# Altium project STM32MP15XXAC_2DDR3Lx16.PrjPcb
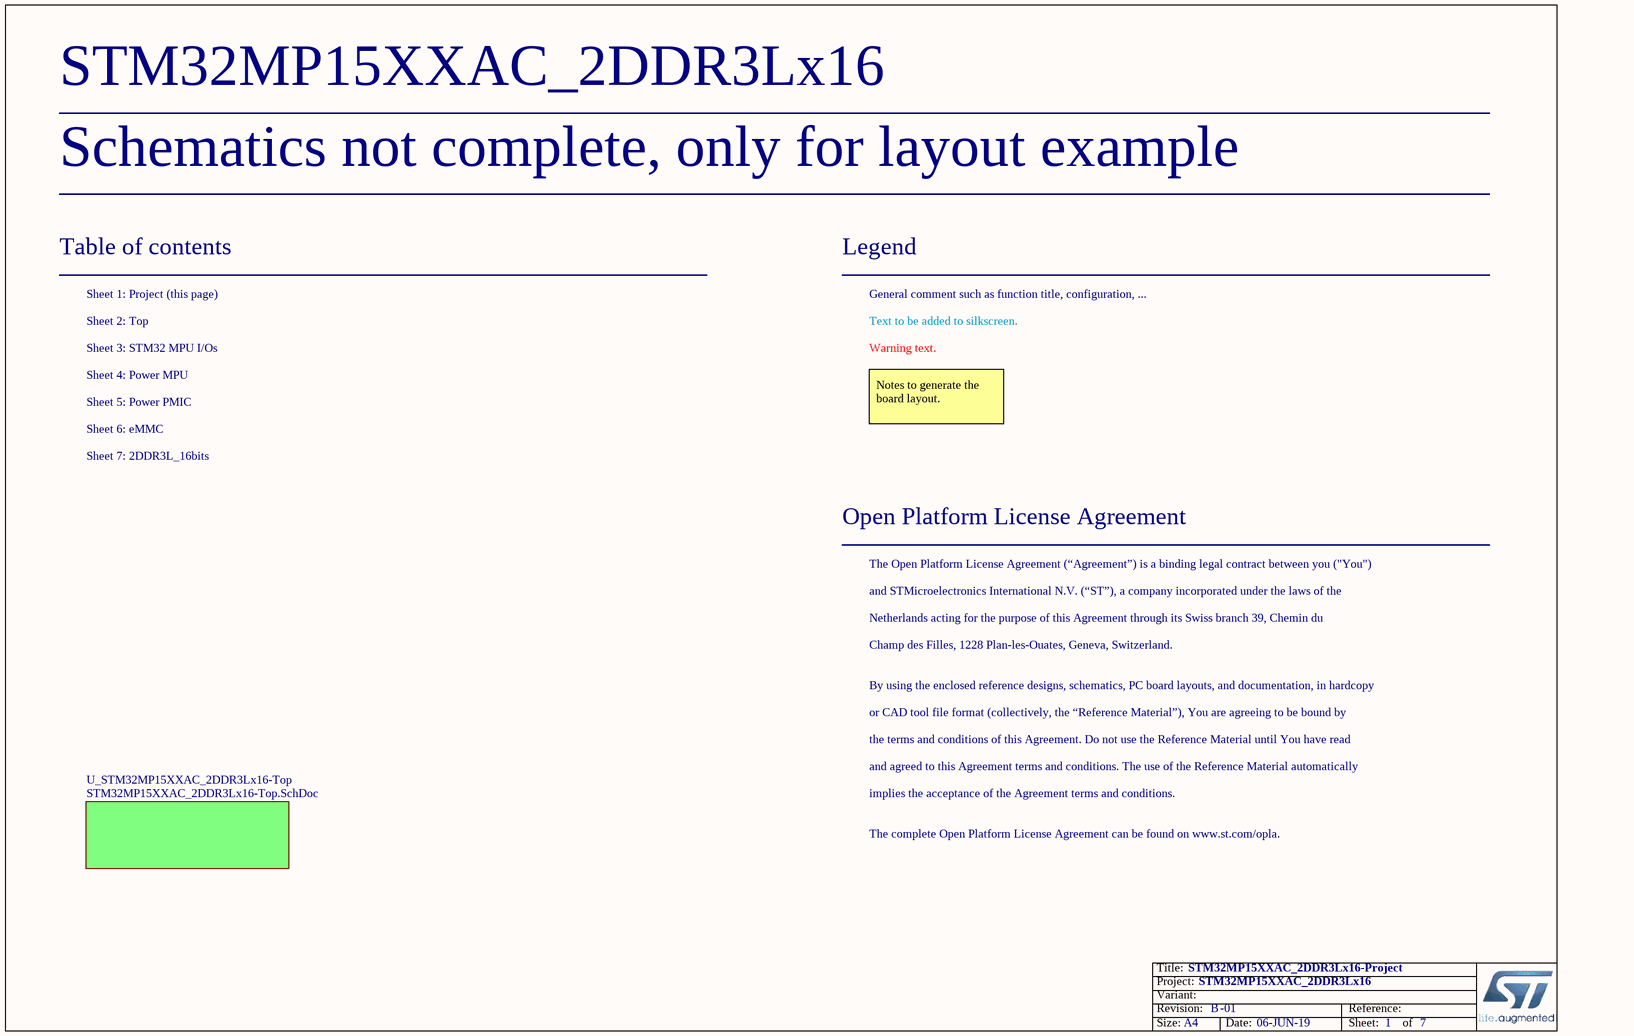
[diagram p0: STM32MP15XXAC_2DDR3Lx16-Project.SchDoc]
Board_PCB_Revision: B; Board_Name: STM32MP15XXAC_2DDR3Lx16; Board_Document_Date: 06-JUN-19; Board_Assembly_Revision: 01
7 sheets, 152 parts. Net scope: flat (ports and power ports of the same name join across sheets).
Board file: STM32MP15XXAC_2DDR3Lx16_B01.PcbDoc
Sheets:
  STM32MP15XXAC_2DDR3Lx16-Project.SchDoc
    U_STM32MP15XXAC_2DDR3Lx16-Top = STM32MP15XXAC_2DDR3Lx16-Top.SchDoc
      U_Power_PMIC = Power_PMIC.SchDoc
      U_Power_MPU = Power_MPU.SchDoc
      U_eMMC = eMMC.SchDoc
      U_STM32_MPU_IOs = STM32_MPU_IOs.SchDoc
      U_2DDR3L_16bits = 2DDR3L_16bits.SchDoc

## Sheet STM32MP15XXAC_2DDR3Lx16-Project.SchDoc: STM32MP15XXAC_2DDR3Lx16-Project
size A4; ApprovedBy: Not used; CheckedBy: Not used; Author: Not used; CompanyName: STMicroelectronics; DrawnBy: Not used; Engineer: Not used; Organization: Not used; Address1: Not used; Address2: Not used; Address3: Not used; Address4: Not used; DocumentNumber: Not used; Revision: Not used; SheetNumber: 1; SheetTotal: 7

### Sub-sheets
U_STM32MP15XXAC_2DDR3Lx16-Top = STM32MP15XXAC_2DDR3Lx16-Top.SchDoc: no entries

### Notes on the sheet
- Schematics not complete, only for layout example
- Table of contents
- Sheet 1: Project (this page)
- Legend
- General comment such as function title, configuration, ...
- Sheet 2: Top
- Sheet 3: STM32 MPU I/Os
- Sheet 4: Power MPU
- Text to be added to silkscreen.
- Warning text.
- Sheet 5: Power PMIC
- Sheet 6: eMMC
- Notes to generate the board layout.
- Sheet 7: 2DDR3L_16bits
- Open Platform License Agreement
- The Open Platform License Agreement (“Agreement”) is a binding legal contract between you ("You")
- and STMicroelectronics International N.V. (“ST”), a company incorporated under the laws of the
- Netherlands acting for the purpose of this Agreement through its Swiss branch 39, Chemin du
- Champ des Filles, 1228 Plan-les-Ouates, Geneva, Switzerland.
- By using the enclosed reference designs, schematics, PC board layouts, and documentation, in hardcopy
- or CAD tool file format (collectively, the “Reference Material”), You are agreeing to be bound by
- the terms and conditions of this Agreement. Do not use the Reference Material until You have read
- and agreed to this Agreement terms and conditions. The use of the Reference Material automatically
- implies the acceptance of the Agreement terms and conditions.
- The complete Open Platform License Agreement can be found on www.st.com/opla.

## Sheet STM32MP15XXAC_2DDR3Lx16-Top.SchDoc: STM32MP15XXAC_2DDR3Lx16-TOP
size A4; Date: Not used; ApprovedBy: Not used; CheckedBy: Not used; Author: Not used; CompanyName: STMicroelectronics; DrawnBy: Not used; Engineer: Not used; Organization: Not used; Address1: Not used; Address2: Not used; Address3: Not used; Address4: Not used; DocumentNumber: Not used; Revision: Not used; SheetNumber: 2; SheetTotal: 7
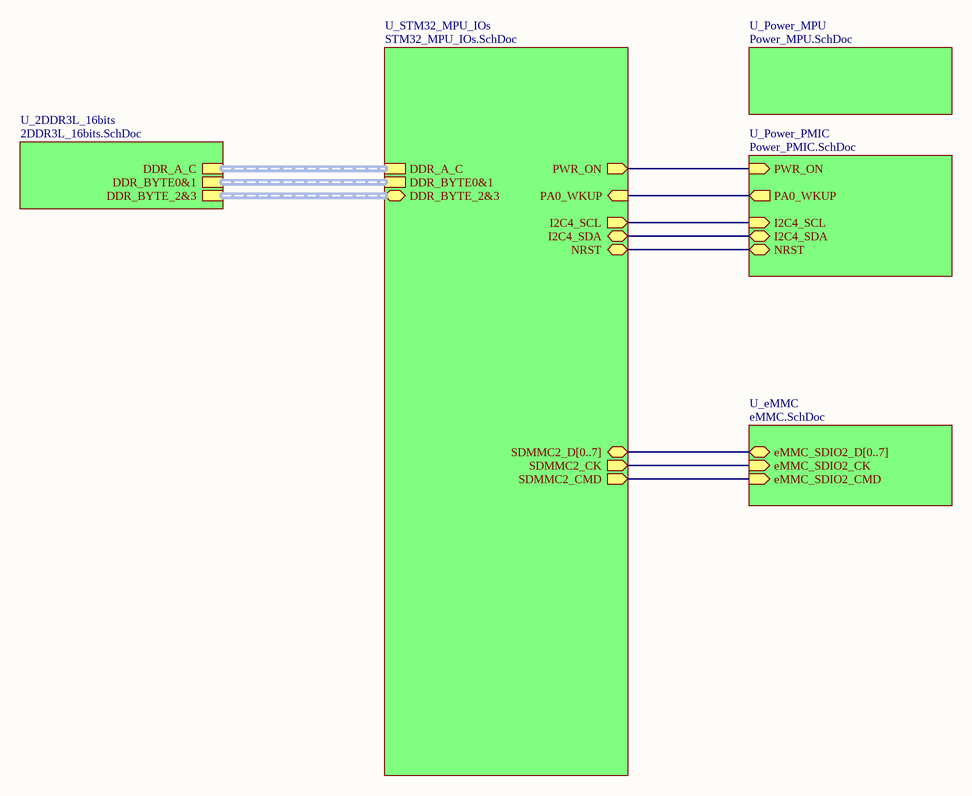
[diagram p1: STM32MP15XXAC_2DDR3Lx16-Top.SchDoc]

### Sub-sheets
U_2DDR3L_16bits = 2DDR3L_16bits.SchDoc: DDR_A_C (harness DDR_A_C), DDR_BYTE0&1 (harness DDR_BYTE_0&1), DDR_BYTE_2&3 (harness DDR_BYTE_2&3)
U_eMMC = eMMC.SchDoc: eMMC_SDIO2_CK (in), eMMC_SDIO2_D[0..7] (bidir), eMMC_SDIO2_CMD (in)
U_Power_MPU = Power_MPU.SchDoc: no entries
U_Power_PMIC = Power_PMIC.SchDoc: I2C4_SDA (bidir), I2C4_SCL (in), PA0_WKUP (out), NRST (bidir), PWR_ON (in)
U_STM32_MPU_IOs = STM32_MPU_IOs.SchDoc: PA0_WKUP (in), NRST (bidir), PWR_ON (out), I2C4_SCL (out), I2C4_SDA (bidir), DDR_BYTE0&1 (harness DDR_BYTE_0&1), DDR_A_C (harness DDR_A_C), SDMMC2_D[0..7] (bidir), SDMMC2_CMD (out), SDMMC2_CK (out), DDR_BYTE_2&3 (harness DDR_BYTE_2&3)

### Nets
(unnamed): sheet U_Power_PMIC/I2C4_SDA, sheet U_STM32_MPU_IOs/I2C4_SDA
(unnamed): sheet U_Power_PMIC/I2C4_SCL, sheet U_STM32_MPU_IOs/I2C4_SCL  [a separate net that carries the same name]
(unnamed): sheet U_Power_PMIC/PA0_WKUP, sheet U_STM32_MPU_IOs/PA0_WKUP  [a separate net that carries the same name]
(unnamed): sheet U_Power_PMIC/NRST, sheet U_STM32_MPU_IOs/NRST  [a separate net that carries the same name]
(unnamed): sheet U_Power_PMIC/PWR_ON, sheet U_STM32_MPU_IOs/PWR_ON  [a separate net that carries the same name]
(unnamed): sheet U_eMMC/eMMC_SDIO2_CK, sheet U_STM32_MPU_IOs/SDMMC2_CK  [a separate net that carries the same name]
(unnamed): sheet U_eMMC/eMMC_SDIO2_CMD, sheet U_STM32_MPU_IOs/SDMMC2_CMD  [a separate net that carries the same name]

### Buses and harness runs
bus sheet U_eMMC/eMMC_SDIO2_D[0..7] = sheet U_STM32_MPU_IOs/SDMMC2_D[0..7]
harness sheet U_2DDR3L_16bits/DDR_A_C = sheet U_STM32_MPU_IOs/DDR_A_C
harness sheet U_2DDR3L_16bits/DDR_BYTE0&1 = sheet U_STM32_MPU_IOs/DDR_BYTE0&1
harness sheet U_2DDR3L_16bits/DDR_BYTE_2&3 = sheet U_STM32_MPU_IOs/DDR_BYTE_2&3

## Sheet Power_PMIC.SchDoc: Power_PMIC
size A3; CompanyName: STMicroelectronics; Organization: Microcontrollers Division; Address1: 12, Rue Jules HOROWITZ; Address2: 38019 Grenoble; Address3: FRANCE; SheetNumber: 5; SheetTotal: 7
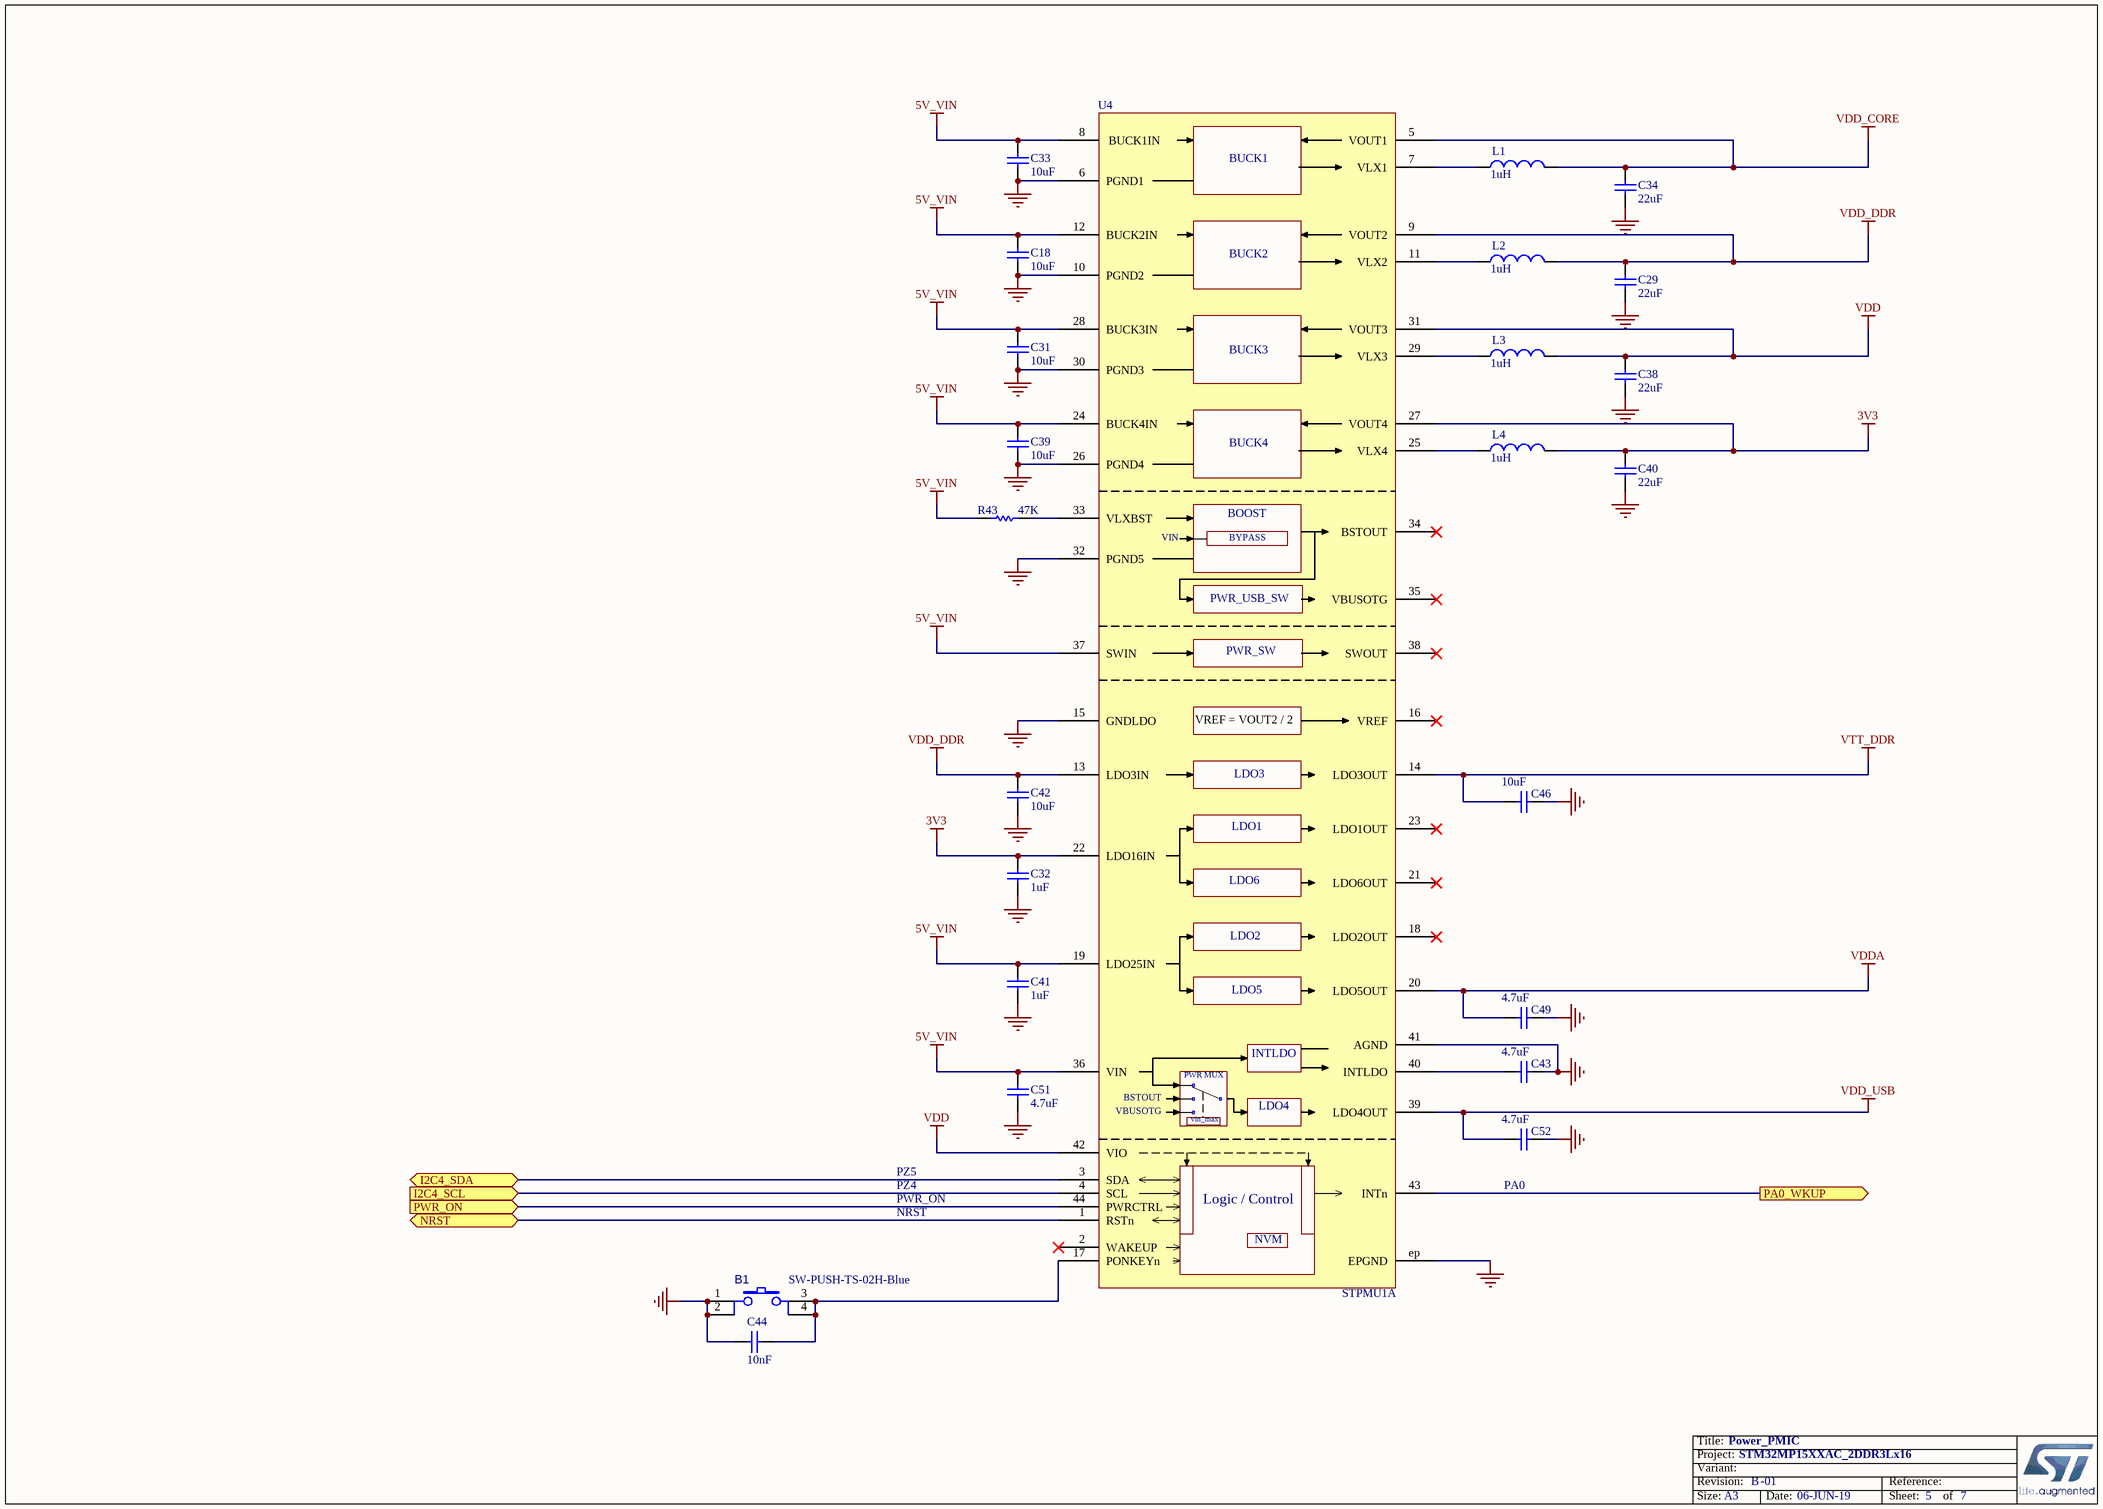
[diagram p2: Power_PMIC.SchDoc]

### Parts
B1  SW-PUSH-TS-02H-Blue  [SWI_JIUBABA_C-TS-02H-2-5-B-V-T_R_BLUE]
C18  value 10uF  [C0603]  (hidden comment: Capacitor)
C29  value 22uF  [C0603]  (hidden comment: Capacitor)
C31  value 10uF  [C0603]  (hidden comment: Capacitor)
C32  value 1uF  [C0402]  (hidden comment: Capacitor)
C33  value 10uF  [C0603]  (hidden comment: Capacitor)
C34  value 22uF  [C0603]  (hidden comment: Capacitor)
C38  value 22uF  [C0603]  (hidden comment: Capacitor)
C39  value 10uF  [C0603]  (hidden comment: Capacitor)
C40  value 22uF  [C0603]  (hidden comment: Capacitor)
C41  value 1uF  [C0402]  (hidden comment: Capacitor)
C42  value 10uF  [C0603]  (hidden comment: Capacitor)
C43  value 4.7uF  [C0402]  (hidden comment: Capacitor)
C44  value 10nF  [C0402]  (hidden comment: Capacitor)
C46  value 10uF  [C0603]  (hidden comment: Capacitor)
C49  value 4.7uF  [C0402]  (hidden comment: Capacitor)
C51  value 4.7uF  [C0402]  (hidden comment: Capacitor)
C52  value 4.7uF  [C0402]  (hidden comment: Capacitor)
L1  value 1uH  [IND_2520_TOKO_DFE252012P]  (hidden comment: IND_1uH_42mohm_3.2A)
L2  value 1uH  [IND_2520_TOKO_DFE252012P]  (hidden comment: IND_1uH_42mohm_3.2A)
L3  value 1uH  [IND_2520_TOKO_DFE252012P]  (hidden comment: IND_1uH_42mohm_3.2A)
L4  value 1uH  [IND_2520_TOKO_DFE252012P]  (hidden comment: IND_1uH_42mohm_3.2A)
R43  value 47K  [R0402]  (hidden comment: Resistor)
U4  value STPMU1A  [ICC_WFQFN44-EPAD_5X6_P040]  (hidden comment: STPMU1)

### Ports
I2C4_SCL (in), I2C4_SDA (bidir), NRST (bidir), PA0_WKUP (out), PWR_ON (in)

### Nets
3V3: C32.2 C40.2 L4.2 U4.22(LDO16IN) U4.27(VOUT4)
5V_VIN: C18.2 C31.2 C33.2 C39.2 C41.2 C51.2 R43.2 U4.8(BUCK1IN) U4.12(BUCK2IN) U4.19(LDO25IN) U4.24(BUCK4IN) U4.28(BUCK3IN) U4.36(VIN) U4.37(SWIN)
GND: B1.1 B1.2 C18.1 C29.1 C31.1 C32.1 C33.1 C34.1 C38.1 C39.1 C40.1 C41.1 C42.1 C43.2 C44.1 C46.1 C49.1 C51.1 C52.1 U4.6(PGND1) U4.10(PGND2) U4.15(GNDLDO) U4.26(PGND4) U4.30(PGND3) U4.32(PGND5) U4.41(AGND) U4.ep(EPGND)
VDD: C38.2 L3.2 U4.31(VOUT3) U4.42(VIO)
VDD_CORE: C34.2 L1.2 U4.5(VOUT1)
VDD_DDR: C29.2 C42.2 L2.2 U4.9(VOUT2) U4.13(LDO3IN)
VDD_USB: C52.2 U4.39(LDO4OUT)
VDDA: C49.2 U4.20(LDO5OUT)
VTT_DDR: C46.2 U4.14(LDO3OUT)
I2C4_SCL: U4.4(SCL) ; port I2C4_SCL
I2C4_SDA: U4.3(SDA) ; port I2C4_SDA
NRST: U4.1(RSTn) ; port NRST
PA0_WKUP: U4.43(INTn) ; port PA0_WKUP
PWR_ON: U4.44(PWRCTRL) ; port PWR_ON
NetB1_3: B1.3 B1.4 C44.2 U4.17(PONKEYn)
NetC43_1: C43.1 U4.40(INTLDO)
NetL1_1: L1.1 U4.7(VLX1)
NetL2_1: L2.1 U4.11(VLX2)
NetL3_1: L3.1 U4.29(VLX3)
NetL4_1: L4.1 U4.25(VLX4)
NetR43_1: R43.1 U4.33(VLXBST)

Not connected (* = marked no-connect by the designer): U4 2(WAKEUP)* 16(VREF)* 18(LDO2OUT)* 21(LDO6OUT)* 23(LDO1OUT)* 34(BSTOUT)* 35(VBUSOTG)* 38(SWOUT)*

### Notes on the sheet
- PZ5
- PZ4
- (near C52) PA0
- NRST
- PWR_ON

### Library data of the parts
B1 = MCD-00172: Switch HW SMD blue; Part_Type: Misc; Manufacturer_Part_Number: C-TS-02H-2.5-B-V-T/R BLUE; Manufacturer: JIUBABA; Provided_By: SUBCO
C18 C31 C33 C39 C42 = MCD-00099: Capacitor, MLCC, 10uF, 10V, X5R, +/-10%, 0603, T=0,8mm; Manufacturer_Part_Number: GRM188R61A106KE69D; Manufacturer: MURATA; Provided_By: SUBCO; Order_Code_RS: 170-6168; ECCN_EU: NEC; ECCN_US: EAR99
C29 C34 C38 C40 = MCD-00100: Capacitor, MLCC, 22uF, 6V3, X5R, +/-20%, 0603, T=0,8mm; Manufacturer_Part_Number: GRM188R60J226MEA0J; Manufacturer: MURATA; Provided_By: SUBCO; ECCN_EU: NEC; ECCN_US: EAR99
C32 C41 = MCD-00095: Capacitor, MLCC, 1uF, 25V, X5R, +/-10%, 0402, T=0,5mm; Manufacturer_Part_Number: GRM155R61E105KA12; Manufacturer: MURATA; Alternate_Manufacturer_Part_Number: GRM155R60J105KE19; Provided_By: SUBCO; Order_Code_RS: 846-7287; ECCN_EU: NEC; ECCN_US: EAR99
C43 C49 C51 C52 = MCD-00096: Capacitor, MLCC, 4.7uF, 6V3, X5R, +/-20%, 0402, T=0,5mm; Manufacturer_Part_Number: GRM155R60J475ME87; Manufacturer: MURATA; Provided_By: SUBCO; Order_Code_RS: 846-7278; ECCN_EU: NEC; ECCN_US: EAR99
C44 = MCD-00011: Capacitor, MLCC, 10nF, 16V, X7R, +/-10%, 0402, T=0.5mm; Manufacturer_Part_Number: CC0402KRX7R7BB103; Manufacturer: YAGEO; Provided_By: SUBCO; Order_Code_RS: 669-8688; ECCN_EU: NEC; ECCN_US: EAR99
C46 = MCD-00099: Capacitor, MLCC, 10uF, 10V, X5R, +/-10%, 0603, T=0,8mm; Manufacturer_Part_Number: GRM188R61A106KE69D; Manufacturer: MURATA; ECCN_US: EAR99; ECCN_EU: NEC; Provided_By: SUBCO; Order_Code_RS: 170-6168
L1-L4 = MCD-01122: Power Inductor ,1uH,4.3A max,+/-20%,0.042ohm,2520; Manufacturer_Part_Number: DFE252012P-1ROM=P2; Manufacturer: MURATA; Provided_By: SUBCO; ECCN_EU: NEC; ECCN_US: EAR99
R43 = MCD-00063: Resistor,47K,0402,1%,1/16W; Manufacturer_Part_Number: RC0402FR-0747KL; Manufacturer: YAGEO; Provided_By: SUBCO; ECCN_EU: NEC; ECCN_US: EAR99
U4 = MCD-00303: STM PMIC WFQFN 5.0x6.0x0.80 44L 0.4 pitch; Part_Type: IC; Manufacturer_Part_Number: STPMU1APQR; Manufacturer: STMICROELECTRONICS; BMS_Part_Number: 9177718; Provided_By: SUBCO with ST control; Company_Nationality: Netherlands; ECCN_EU: NEC; ECCN_US: EAR99

## Sheet Power_MPU.SchDoc: Power_MPU
size A3; CompanyName: STMicroelectronics; SheetNumber: 4; SheetTotal: 7
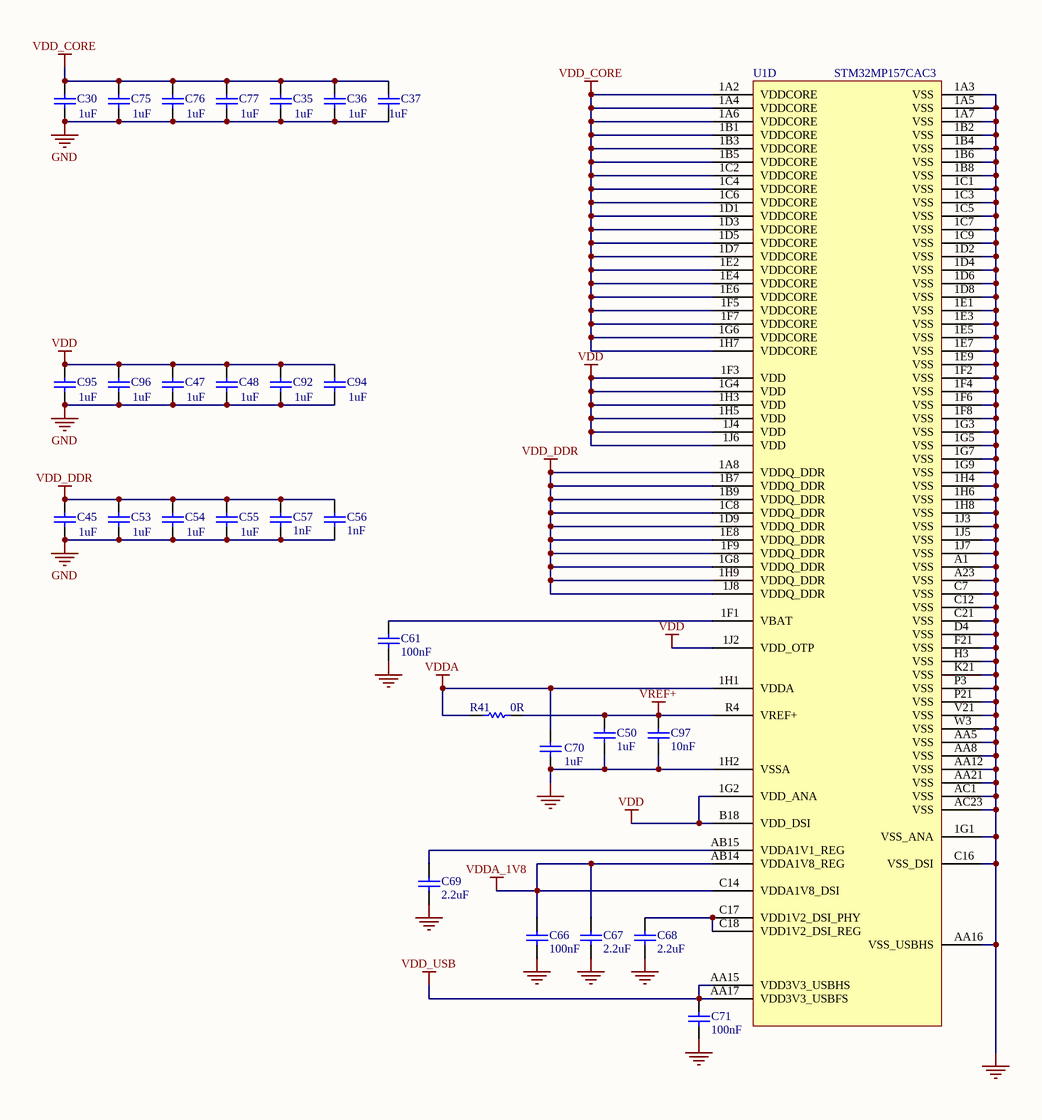
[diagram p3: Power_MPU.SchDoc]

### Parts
C30  value 1uF  [C0402]  (hidden comment: Capacitor)
C35  value 1uF  [C0402]  (hidden comment: Capacitor)
C36  value 1uF  [C0402]  (hidden comment: Capacitor)
C37  value 1uF  [C0402]  (hidden comment: Capacitor)
C45  value 1uF  [C0402]  (hidden comment: Capacitor)
C47  value 1uF  [C0402]  (hidden comment: Capacitor)
C48  value 1uF  [C0402]  (hidden comment: Capacitor)
C50  value 1uF  [C0402]  (hidden comment: Capacitor)
C53  value 1uF  [C0402]  (hidden comment: Capacitor)
C54  value 1uF  [C0402]  (hidden comment: Capacitor)
C55  value 1uF  [C0402]  (hidden comment: Capacitor)
C56  value 1nF  [C0402]  (hidden comment: Capacitor)
C57  value 1nF  [C0402]  (hidden comment: Capacitor)
C61  value 100nF  [C0402]  (hidden comment: Capacitor)
C66  value 100nF  [C0402]  (hidden comment: Capacitor)
C67  value 2.2uF  [C0402]  (hidden comment: Capacitor)
C68  value 2.2uF  [C0402]  (hidden comment: Capacitor)
C69  value 2.2uF  [C0402]  (hidden comment: Capacitor)
C70  value 1uF  [C0402]  (hidden comment: Capacitor)
C71  value 100nF  [C0402]  (hidden comment: Capacitor)
C75  value 1uF  [C0402]  (hidden comment: Capacitor)
C76  value 1uF  [C0402]  (hidden comment: Capacitor)
C77  value 1uF  [C0402]  (hidden comment: Capacitor)
C92  value 1uF  [C0402]  (hidden comment: Capacitor)
C94  value 1uF  [C0402]  (hidden comment: Capacitor)
C95  value 1uF  [C0402]  (hidden comment: Capacitor)
C96  value 1uF  [C0402]  (hidden comment: Capacitor)
C97  value 10nF  [C0402]  (hidden comment: Capacitor)
R41  value 0R  [R0402]  (hidden comment: Resistor)
U1  STM32MP157CAC3  [ICC_TFBGA361_12X12_STM32MP157CAC3_P050-065]  (part D of 5)

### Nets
GND: C30.1 C35.1 C36.1 C37.1 C45.1 C47.1 C48.1 C50.1 C53.1 C54.1 C55.1 C56.1 C57.1 C61.1 C66.1 C67.1 C68.1 C69.1 C70.1 C71.1 C75.1 C76.1 C77.1 C92.1 C94.1 C95.1 C96.1 C97.1 U1.1A3(VSS) U1.1A5(VSS) U1.1A7(VSS) U1.1B2(VSS) U1.1B4(VSS) U1.1B6(VSS) U1.1B8(VSS) U1.1C1(VSS) U1.1C3(VSS) U1.1C5(VSS) U1.1C7(VSS) U1.1C9(VSS) U1.1D2(VSS) U1.1D4(VSS) U1.1D6(VSS) U1.1D8(VSS) U1.1E1(VSS) U1.1E3(VSS) U1.1E5(VSS) U1.1E7(VSS) U1.1E9(VSS) U1.1F2(VSS) U1.1F4(VSS) U1.1F6(VSS) U1.1F8(VSS) U1.1G1(VSS_ANA) U1.1G3(VSS) U1.1G5(VSS) U1.1G7(VSS) U1.1G9(VSS) U1.1H2(VSSA) U1.1H4(VSS) U1.1H6(VSS) U1.1H8(VSS) U1.1J3(VSS) U1.1J5(VSS) U1.1J7(VSS) U1.A1(VSS) U1.A23(VSS) U1.AA5(VSS) U1.AA8(VSS) U1.AA12(VSS) U1.AA16(VSS_USBHS) U1.AA21(VSS) U1.AC1(VSS) U1.AC23(VSS) U1.C7(VSS) U1.C12(VSS) U1.C16(VSS_DSI) U1.C21(VSS) U1.D4(VSS) U1.F21(VSS) U1.H3(VSS) U1.K21(VSS) U1.P3(VSS) U1.P21(VSS) U1.V21(VSS) U1.W3(VSS)
VDD: C47.2 C48.2 C92.2 C94.2 C95.2 C96.2 U1.1F3(VDD) U1.1G2(VDD_ANA) U1.1G4(VDD) U1.1H3(VDD) U1.1H5(VDD) U1.1J2(VDD_OTP) U1.1J4(VDD) U1.1J6(VDD) U1.B18(VDD_DSI)
VDD_CORE: C30.2 C35.2 C36.2 C37.2 C75.2 C76.2 C77.2 U1.1A2(VDDCORE) U1.1A4(VDDCORE) U1.1A6(VDDCORE) U1.1B1(VDDCORE) U1.1B3(VDDCORE) U1.1B5(VDDCORE) U1.1C2(VDDCORE) U1.1C4(VDDCORE) U1.1C6(VDDCORE) U1.1D1(VDDCORE) U1.1D3(VDDCORE) U1.1D5(VDDCORE) U1.1D7(VDDCORE) U1.1E2(VDDCORE) U1.1E4(VDDCORE) U1.1E6(VDDCORE) U1.1F5(VDDCORE) U1.1F7(VDDCORE) U1.1G6(VDDCORE) U1.1H7(VDDCORE)
VDD_DDR: C45.2 C53.2 C54.2 C55.2 C56.2 C57.2 U1.1A8(VDDQ_DDR) U1.1B7(VDDQ_DDR) U1.1B9(VDDQ_DDR) U1.1C8(VDDQ_DDR) U1.1D9(VDDQ_DDR) U1.1E8(VDDQ_DDR) U1.1F9(VDDQ_DDR) U1.1G8(VDDQ_DDR) U1.1H9(VDDQ_DDR) U1.1J8(VDDQ_DDR)
VDD_USB: C71.2 U1.AA15(VDD3V3_USBHS) U1.AA17(VDD3V3_USBFS)
VDDA: C70.2 R41.1 U1.1H1(VDDA)
VDDA_1V8: C66.2 C67.2 U1.AB14(VDDA1V8_REG) U1.C14(VDDA1V8_DSI)
VREF+: C50.2 C97.2 R41.2 U1.R4(VREF+)
NetC61_2: C61.2 U1.1F1(VBAT)
NetC68_2: C68.2 U1.C17(VDD1V2_DSI_PHY) U1.C18(VDD1V2_DSI_REG)
NetC69_2: C69.2 U1.AB15(VDDA1V1_REG)

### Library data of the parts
C30 C35-C37 C45 C47 C48 C50 C53-C55 C70 C75-C77 C92 C94-C96 = MCD-00095: Capacitor, MLCC, 1uF, 25V, X5R, +/-10%, 0402, T=0,5mm; Manufacturer_Part_Number: GRM155R61E105KA12; Manufacturer: MURATA; Alternate_Manufacturer_Part_Number: GRM155R60J105KE19; ECCN_US: EAR99; ECCN_EU: NEC; Provided_By: SUBCO; Order_Code_RS: 846-7287
C56 C57 = MCD-00198: Capacitor, MLCC, 1nF, 16V, X7R, +/-10%, 0402, T=0.5mm; Manufacturer_Part_Number: CC0402KRX7R7BB102; Manufacturer: YAGEO; Provided_By: SUBCO; ECCN_EU: NEC; ECCN_US: EAR99
C61 C71 = MCD-00006: Capacitor, MLCC, 100nF, 16V, X7R, +/-10%, 0402, T=0.5mm; Manufacturer_Part_Number: CC0402KRX7R7BB104; Manufacturer: YAGEO; Alternate_Manufacturer: MURATA; Alternate_Manufacturer_Part_Number: GCM155R71C104KA55D; ECCN_US: EAR99; ECCN_EU: NEC; Provided_By: SUBCO; Order_Code_RS: 616-9701
C66 = MCD-00006: Capacitor, MLCC, 100nF, 16V, X7R, +/-10%, 0402, T=0.5mm; Manufacturer_Part_Number: CC0402KRX7R7BB104; Manufacturer: YAGEO; Alternate_Manufacturer_Part_Number: GCM155R71C104KA55D; Alternate_Manufacturer: MURATA; ECCN_US: EAR99; ECCN_EU: NEC; Provided_By: SUBCO; Order_Code_RS: 616-9701
C67-C69 = MCD-01823: Capacitor,MLCC, 2.2uF, 6V3, X5R,+/-10%, 0402, T=0.5mm; Manufacturer_Part_Number: GRM155R60J225KE95D; Manufacturer: MURATA; ECCN_US: EAR99; ECCN_EU: NEC; Provided_By: SUBCO; Order_Code_RS: 172-6478
C97 = MCD-00011: Capacitor, MLCC, 10nF, 16V, X7R, +/-10%, 0402, T=0.5mm; Manufacturer_Part_Number: CC0402KRX7R7BB103; Manufacturer: YAGEO; ECCN_US: EAR99; ECCN_EU: NEC; Provided_By: SUBCO; Order_Code_RS: 669-8688
R41 = MCD-00052: Resistor,0R,0402,5%,1/16W; Manufacturer_Part_Number: RC0402JR-070RL; Manufacturer: YAGEO; ECCN_US: EAR99; ECCN_EU: NEC; Provided_By: SUBCO; Order_Code_RS: 618-5804
U1 = MCD-00677: MPU TFBGA12x12 secure boot+crypto; Part_Type: IC; Manufacturer: STMICROELECTRONICS; BMS_Part_Number: 9175503; ECCN_US: 5A002A4; ECCN_EU: NEC; Provided_By: SUBCO with ST control; Company_Nationality: Netherlands

## Sheet eMMC.SchDoc: eMMC
size A3; CompanyName: STMicroelectronics; Address1: 12, Rue Jules HOROWITZ; Address2: 38019 Grenoble; Address3: FRANCE; SheetNumber: 6; SheetTotal: 7
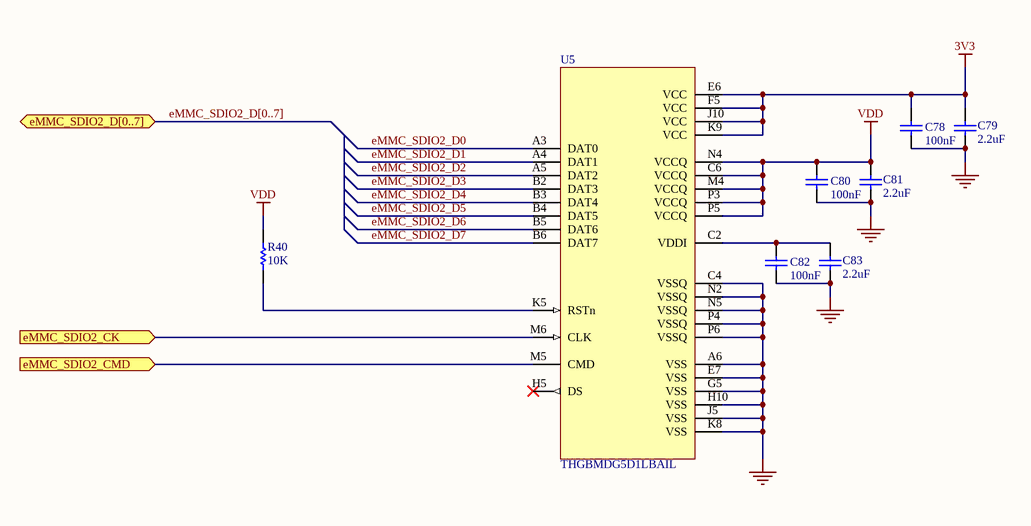
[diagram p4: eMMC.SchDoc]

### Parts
C78  value 100nF  [C0402]  (hidden comment: Capacitor)
C79  value 2.2uF  [C0603]  (hidden comment: Capacitor)
C80  value 100nF  [C0402]  (hidden comment: Capacitor)
C81  value 2.2uF  [C0603]  (hidden comment: Capacitor)
C82  value 100nF  [C0402]  (hidden comment: Capacitor)
C83  value 2.2uF  [C0603]  (hidden comment: Capacitor)
R40  value 10K  [R0402]  (hidden comment: Resistor)
U5  value THGBMDG5D1LBAIL  [ICC_P-WFBGA153_13X11P5_P050]  (hidden comment: eMMC_THGBMDG5D1LBAIL)

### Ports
eMMC_SDIO2_CK (in), eMMC_SDIO2_CMD (in), eMMC_SDIO2_D[0..7] (bidir)

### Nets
3V3: C78.2 C79.2 U5.E6(VCC) U5.F5(VCC) U5.J10(VCC) U5.K9(VCC)
GND: C78.1 C79.1 C80.1 C81.1 C82.1 C83.1 U5.A6(VSS) U5.C4(VSSQ) U5.E7(VSS) U5.G5(VSS) U5.H10(VSS) U5.J5(VSS) U5.K8(VSS) U5.N2(VSSQ) U5.N5(VSSQ) U5.P4(VSSQ) U5.P6(VSSQ)
VDD: C80.2 C81.2 R40.2 U5.C6(VCCQ) U5.M4(VCCQ) U5.N4(VCCQ) U5.P3(VCCQ) U5.P5(VCCQ)
eMMC_SDIO2_CK: U5.M6(CLK) ; port eMMC_SDIO2_CK
eMMC_SDIO2_CMD: U5.M5(CMD) ; port eMMC_SDIO2_CMD
eMMC_SDIO2_D0: U5.A3(DAT0)
eMMC_SDIO2_D1: U5.A4(DAT1)
eMMC_SDIO2_D2: U5.A5(DAT2)
eMMC_SDIO2_D3: U5.B2(DAT3)
eMMC_SDIO2_D4: U5.B3(DAT4)
eMMC_SDIO2_D5: U5.B4(DAT5)
eMMC_SDIO2_D6: U5.B5(DAT6)
eMMC_SDIO2_D7: U5.B6(DAT7)
NetC82_2: C82.2 C83.2 U5.C2(VDDI)
NetR40_1: R40.1 U5.K5(RSTn)

Not connected (* = marked no-connect by the designer): U5 H5(DS)*

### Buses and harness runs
bus eMMC_SDIO2_D[0..7] = port eMMC_SDIO2_D[0..7]

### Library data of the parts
C78 C80 C82 = MCD-00006: Capacitor, MLCC, 100nF, 16V, X7R, +/-10%, 0402, T=0.5mm; Manufacturer_Part_Number: CC0402KRX7R7BB104; Manufacturer: YAGEO; Alternate_Manufacturer: MURATA; Alternate_Manufacturer_Part_Number: GCM155R71C104KA55D; Provided_By: SUBCO; Order_Code_RS: 616-9701; ECCN_EU: NEC; ECCN_US: EAR99
C79 C81 C83 = MCD-00012: Capacitor, MLCC, 2.2uF, 10V, X5R, +/- 10%, 0603, T=0,8mm; Manufacturer_Part_Number: CC0603KRX5R6BB225; Manufacturer: YAGEO; Alternate_Manufacturer_Part_Number: C0603C225K8PACTU; Alternate_Manufacturer: KEMET; BMS_Part_Number: 9142010; Provided_By: SUBCO; ECCN_EU: NEC; ECCN_US: EAR99
R40 = MCD-00053: Resistor,10K,0402,1%,1/16W; Manufacturer_Part_Number: RC0402FR-0710KL; Manufacturer: YAGEO; BMS_Part_Number: 9131590; Provided_By: SUBCO; ECCN_EU: NEC; ECCN_US: EAR99
U5 = MCD-00110: Memory,e-MMC,4GB,3V3,WFBGA,153pins; Part_Type: IC; Manufacturer: TOSHIBA; BMS_Part_Number: 9171005; Provided_By: SUBCO; ECCN_EU: NEC; ECCN_US: 3A991

## Sheet STM32_MPU_IOs.SchDoc: MPU
size A3; SheetNumber: 3; SheetTotal: 7
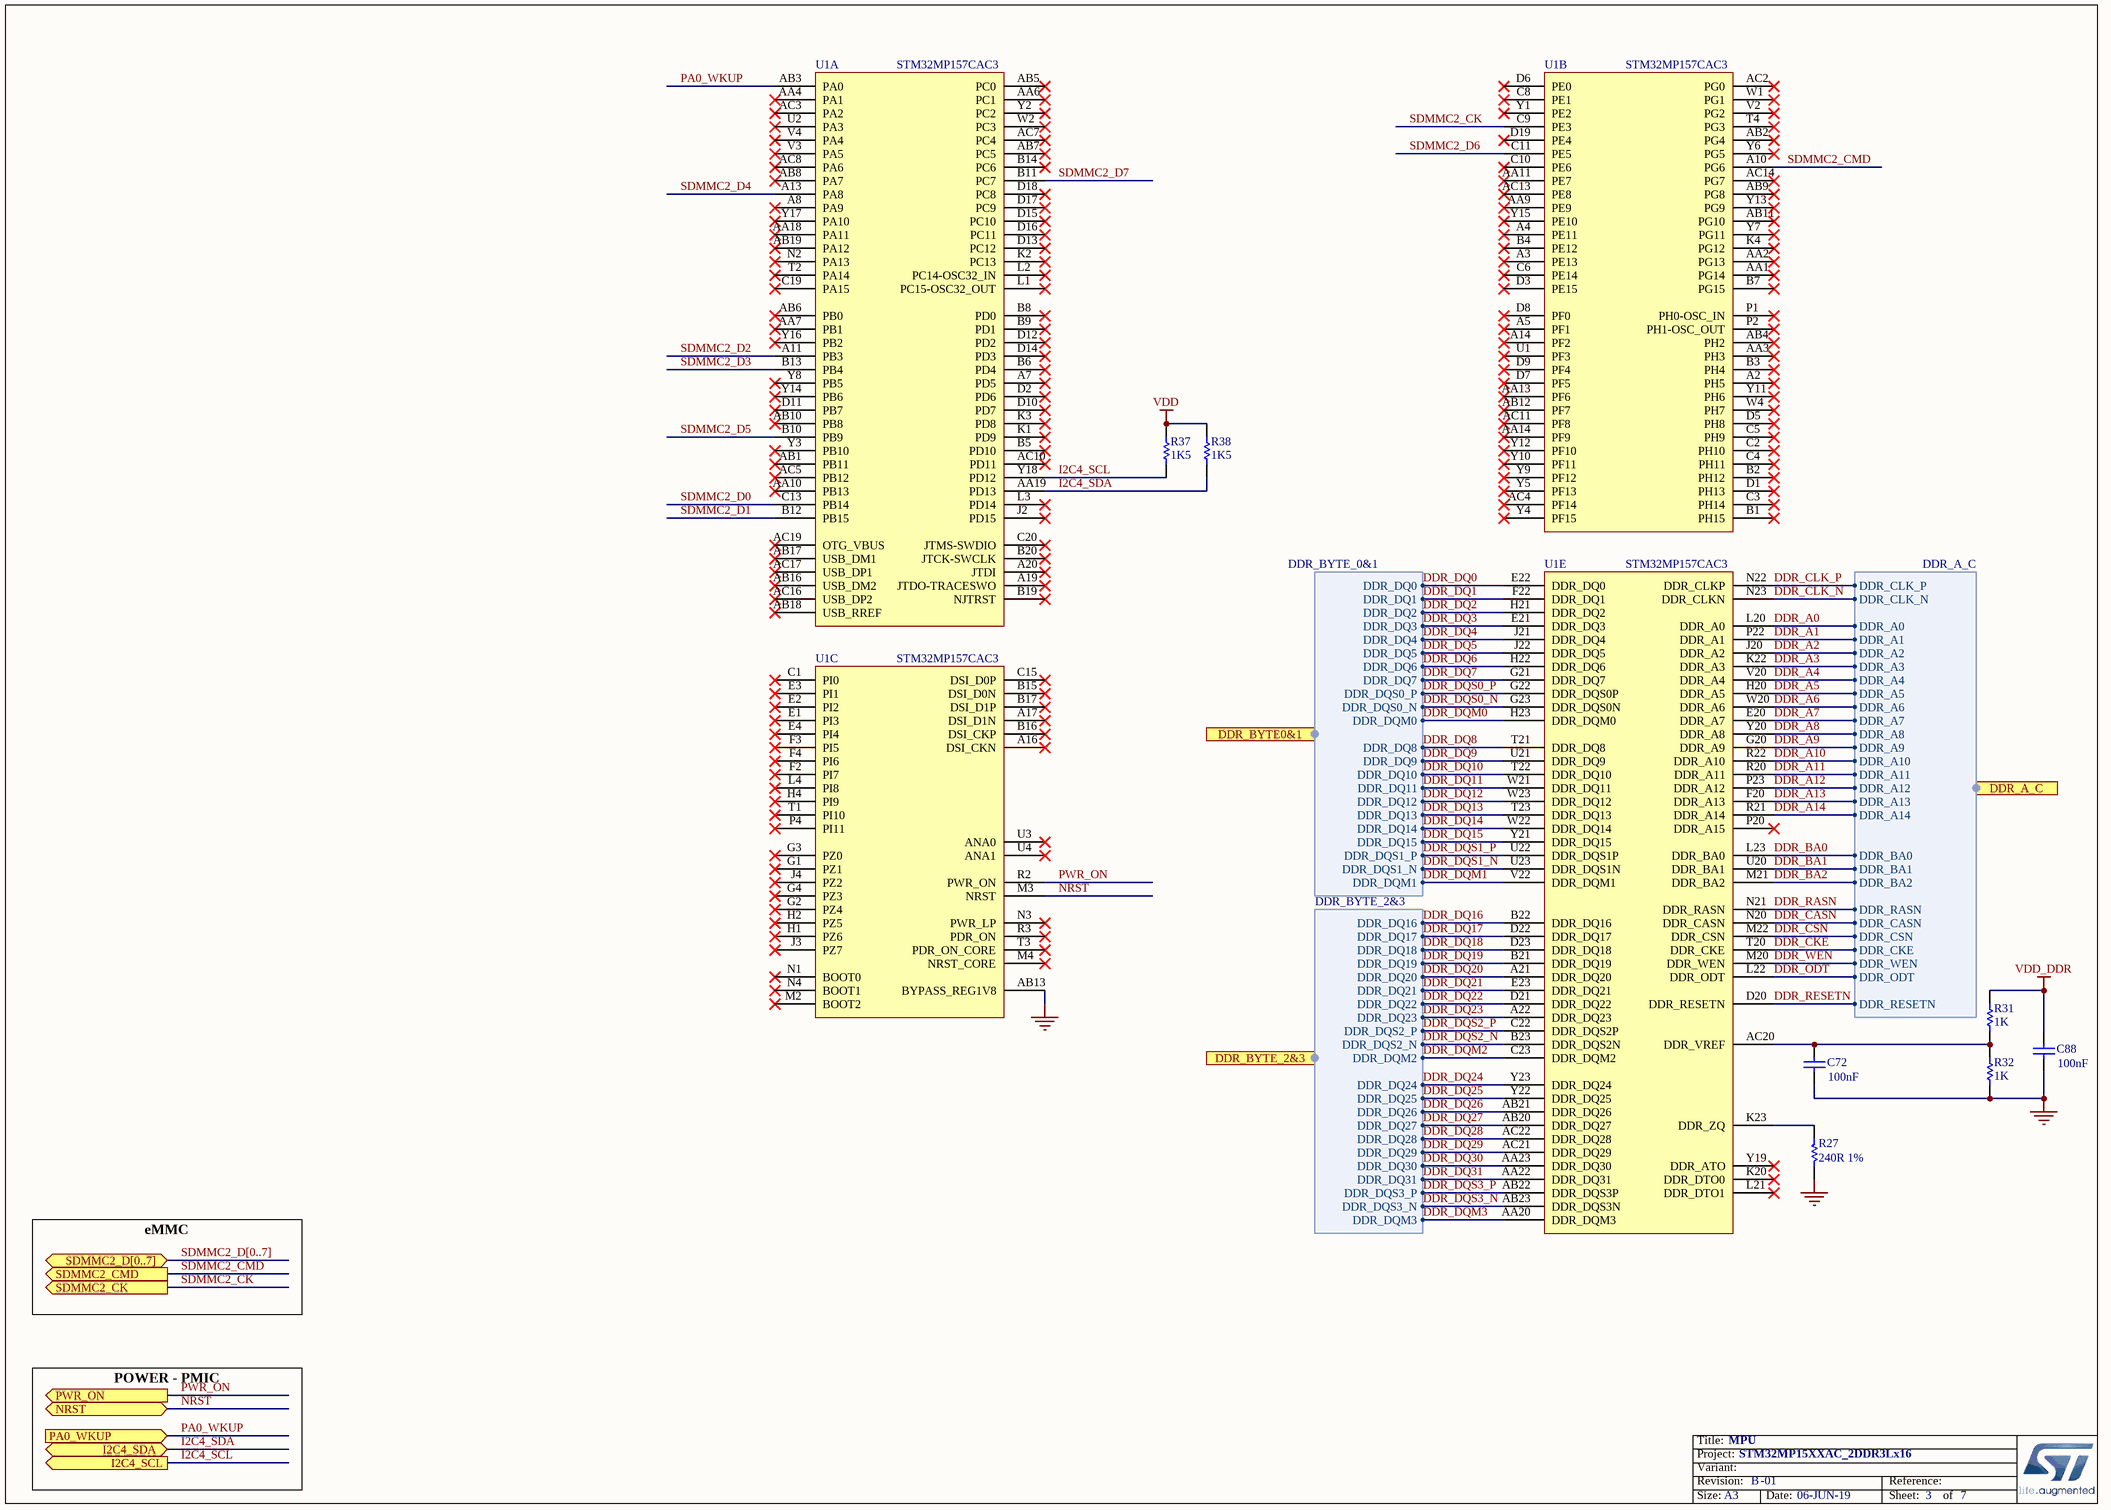
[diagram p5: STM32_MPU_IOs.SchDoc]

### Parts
C72  value 100nF  [C0402]  (hidden comment: Capacitor)
C88  value 100nF  [C0402]  (hidden comment: Capacitor)
R27  value 240R 1%  [R0402]  (hidden comment: Resistor)
R31  value 1K  [R0402]  (hidden comment: Resistor)
R32  value 1K  [R0402]  (hidden comment: Resistor)
R37  value 1K5  [R0402]  (hidden comment: Resistor)
R38  value 1K5  [R0402]  (hidden comment: Resistor)
U1  STM32MP157CAC3  [ICC_TFBGA361_12X12_STM32MP157CAC3_P050-065]  (parts A,B,C,E of 5)

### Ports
DDR_A_C (harness DDR_A_C), DDR_BYTE0&1 (harness DDR_BYTE_0&1), DDR_BYTE_2&3 (harness DDR_BYTE_2&3), I2C4_SCL (out), I2C4_SDA (bidir), NRST (bidir), PA0_WKUP (in), PWR_ON (out), SDMMC2_CK (out), SDMMC2_CMD (out), SDMMC2_D[0..7] (bidir)

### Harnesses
DDR_BYTE_0&1: DDR_DQ0, DDR_DQ1, DDR_DQ2, DDR_DQ3, DDR_DQ4, DDR_DQ5, DDR_DQ6, DDR_DQ7, DDR_DQS0_P, DDR_DQS0_N, DDR_DQM0, DDR_DQ8, DDR_DQ9, DDR_DQ10, DDR_DQ11, DDR_DQ12, DDR_DQ13, DDR_DQ14, DDR_DQ15, DDR_DQS1_P, DDR_DQS1_N, DDR_DQM1
DDR_A_C: DDR_CLK_P, DDR_CLK_N, DDR_A0, DDR_A1, DDR_A2, DDR_A3, DDR_A4, DDR_A5, DDR_A6, DDR_A7, DDR_A8, DDR_A9, DDR_A10, DDR_A11, DDR_A12, DDR_A13, DDR_A14, DDR_BA0, DDR_BA1, DDR_BA2, DDR_RASN, DDR_CASN, DDR_CSN, DDR_CKE, DDR_WEN, DDR_ODT, DDR_RESETN
DDR_BYTE_2&3: DDR_DQ16, DDR_DQ17, DDR_DQ18, DDR_DQ19, DDR_DQ20, DDR_DQ21, DDR_DQ22, DDR_DQ23, DDR_DQS2_P, DDR_DQS2_N, DDR_DQM2, DDR_DQ24, DDR_DQ25, DDR_DQ26, DDR_DQ27, DDR_DQ28, DDR_DQ29, DDR_DQ30, DDR_DQ31, DDR_DQS3_P, DDR_DQS3_N, DDR_DQM3

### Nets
GND: C72.1 C88.1 R27.2 R32.1 U1.AB13(BYPASS_REG1V8)
VDD: R37.1 R38.1
VDD_DDR: C88.2 R31.2
DDR_A0: U1.L20(DDR_A0) ; port DDR_A_C.DDR_A0
DDR_A1: U1.P22(DDR_A1) ; port DDR_A_C.DDR_A1
DDR_A2: U1.J20(DDR_A2) ; port DDR_A_C.DDR_A2
DDR_A3: U1.K22(DDR_A3) ; port DDR_A_C.DDR_A3
DDR_A4: U1.V20(DDR_A4) ; port DDR_A_C.DDR_A4
DDR_A5: U1.H20(DDR_A5) ; port DDR_A_C.DDR_A5
DDR_A6: U1.W20(DDR_A6) ; port DDR_A_C.DDR_A6
DDR_A7: U1.E20(DDR_A7) ; port DDR_A_C.DDR_A7
DDR_A8: U1.Y20(DDR_A8) ; port DDR_A_C.DDR_A8
DDR_A9: U1.G20(DDR_A9) ; port DDR_A_C.DDR_A9
DDR_A10: U1.R22(DDR_A10) ; port DDR_A_C.DDR_A10
DDR_A11: U1.R20(DDR_A11) ; port DDR_A_C.DDR_A11
DDR_A12: U1.P23(DDR_A12) ; port DDR_A_C.DDR_A12
DDR_A13: U1.F20(DDR_A13) ; port DDR_A_C.DDR_A13
DDR_A14: U1.R21(DDR_A14) ; port DDR_A_C.DDR_A14
DDR_BA0: U1.L23(DDR_BA0) ; port DDR_A_C.DDR_BA0
DDR_BA1: U1.U20(DDR_BA1) ; port DDR_A_C.DDR_BA1
DDR_BA2: U1.M21(DDR_BA2) ; port DDR_A_C.DDR_BA2
DDR_CASN: U1.N20(DDR_CASN) ; port DDR_A_C.DDR_CASN
DDR_CKE: U1.T20(DDR_CKE) ; port DDR_A_C.DDR_CKE
DDR_CLK_N: U1.N23(DDR_CLKN) ; port DDR_A_C.DDR_CLK_N
DDR_CLK_P: U1.N22(DDR_CLKP) ; port DDR_A_C.DDR_CLK_P
DDR_CSN: U1.M22(DDR_CSN) ; port DDR_A_C.DDR_CSN
DDR_DQ0: U1.E22(DDR_DQ0) ; port DDR_BYTE0&1.DDR_DQ0
DDR_DQ1: U1.F22(DDR_DQ1) ; port DDR_BYTE0&1.DDR_DQ1
DDR_DQ2: U1.H21(DDR_DQ2) ; port DDR_BYTE0&1.DDR_DQ2
DDR_DQ3: U1.E21(DDR_DQ3) ; port DDR_BYTE0&1.DDR_DQ3
DDR_DQ4: U1.J21(DDR_DQ4) ; port DDR_BYTE0&1.DDR_DQ4
DDR_DQ5: U1.J22(DDR_DQ5) ; port DDR_BYTE0&1.DDR_DQ5
DDR_DQ6: U1.H22(DDR_DQ6) ; port DDR_BYTE0&1.DDR_DQ6
DDR_DQ7: U1.G21(DDR_DQ7) ; port DDR_BYTE0&1.DDR_DQ7
DDR_DQ8: U1.T21(DDR_DQ8) ; port DDR_BYTE0&1.DDR_DQ8
DDR_DQ9: U1.U21(DDR_DQ9) ; port DDR_BYTE0&1.DDR_DQ9
DDR_DQ10: U1.T22(DDR_DQ10) ; port DDR_BYTE0&1.DDR_DQ10
DDR_DQ11: U1.W21(DDR_DQ11) ; port DDR_BYTE0&1.DDR_DQ11
DDR_DQ12: U1.W23(DDR_DQ12) ; port DDR_BYTE0&1.DDR_DQ12
DDR_DQ13: U1.T23(DDR_DQ13) ; port DDR_BYTE0&1.DDR_DQ13
DDR_DQ14: U1.W22(DDR_DQ14) ; port DDR_BYTE0&1.DDR_DQ14
DDR_DQ15: U1.Y21(DDR_DQ15) ; port DDR_BYTE0&1.DDR_DQ15
DDR_DQ16: U1.B22(DDR_DQ16) ; port DDR_BYTE_2&3.DDR_DQ16
DDR_DQ17: U1.D22(DDR_DQ17) ; port DDR_BYTE_2&3.DDR_DQ17
DDR_DQ18: U1.D23(DDR_DQ18) ; port DDR_BYTE_2&3.DDR_DQ18
DDR_DQ19: U1.B21(DDR_DQ19) ; port DDR_BYTE_2&3.DDR_DQ19
DDR_DQ20: U1.A21(DDR_DQ20) ; port DDR_BYTE_2&3.DDR_DQ20
DDR_DQ21: U1.E23(DDR_DQ21) ; port DDR_BYTE_2&3.DDR_DQ21
DDR_DQ22: U1.D21(DDR_DQ22) ; port DDR_BYTE_2&3.DDR_DQ22
DDR_DQ23: U1.A22(DDR_DQ23) ; port DDR_BYTE_2&3.DDR_DQ23
DDR_DQ24: U1.Y23(DDR_DQ24) ; port DDR_BYTE_2&3.DDR_DQ24
DDR_DQ25: U1.Y22(DDR_DQ25) ; port DDR_BYTE_2&3.DDR_DQ25
DDR_DQ26: U1.AB21(DDR_DQ26) ; port DDR_BYTE_2&3.DDR_DQ26
DDR_DQ27: U1.AB20(DDR_DQ27) ; port DDR_BYTE_2&3.DDR_DQ27
DDR_DQ28: U1.AC22(DDR_DQ28) ; port DDR_BYTE_2&3.DDR_DQ28
DDR_DQ29: U1.AC21(DDR_DQ29) ; port DDR_BYTE_2&3.DDR_DQ29
DDR_DQ30: U1.AA23(DDR_DQ30) ; port DDR_BYTE_2&3.DDR_DQ30
DDR_DQ31: U1.AA22(DDR_DQ31) ; port DDR_BYTE_2&3.DDR_DQ31
DDR_DQM0: U1.H23(DDR_DQM0) ; port DDR_BYTE0&1.DDR_DQM0
DDR_DQM1: U1.V22(DDR_DQM1) ; port DDR_BYTE0&1.DDR_DQM1
DDR_DQM2: U1.C23(DDR_DQM2) ; port DDR_BYTE_2&3.DDR_DQM2
DDR_DQM3: U1.AA20(DDR_DQM3) ; port DDR_BYTE_2&3.DDR_DQM3
DDR_DQS0_N: U1.G23(DDR_DQS0N) ; port DDR_BYTE0&1.DDR_DQS0_N
DDR_DQS0_P: U1.G22(DDR_DQS0P) ; port DDR_BYTE0&1.DDR_DQS0_P
DDR_DQS1_N: U1.U23(DDR_DQS1N) ; port DDR_BYTE0&1.DDR_DQS1_N
DDR_DQS1_P: U1.U22(DDR_DQS1P) ; port DDR_BYTE0&1.DDR_DQS1_P
DDR_DQS2_N: U1.B23(DDR_DQS2N) ; port DDR_BYTE_2&3.DDR_DQS2_N
DDR_DQS2_P: U1.C22(DDR_DQS2P) ; port DDR_BYTE_2&3.DDR_DQS2_P
DDR_DQS3_N: U1.AB23(DDR_DQS3N) ; port DDR_BYTE_2&3.DDR_DQS3_N
DDR_DQS3_P: U1.AB22(DDR_DQS3P) ; port DDR_BYTE_2&3.DDR_DQS3_P
DDR_ODT: U1.L22(DDR_ODT) ; port DDR_A_C.DDR_ODT
DDR_RASN: U1.N21(DDR_RASN) ; port DDR_A_C.DDR_RASN
DDR_RESETN: U1.D20(DDR_RESETN) ; port DDR_A_C.DDR_RESETN
DDR_WEN: U1.M20(DDR_WEN) ; port DDR_A_C.DDR_WEN
I2C4_SCL: R37.2 U1.Y18(PD12) ; port I2C4_SCL
I2C4_SDA: R38.2 U1.AA19(PD13) ; port I2C4_SDA
NRST: U1.M3(NRST) ; port NRST
PA0_WKUP: U1.AB3(PA0) ; port PA0_WKUP
PWR_ON: U1.R2(PWR_ON) ; port PWR_ON
SDMMC2_CK: U1.C9(PE3) ; port SDMMC2_CK
SDMMC2_CMD: U1.A10(PG6) ; port SDMMC2_CMD
SDMMC2_D0: U1.C13(PB14)
SDMMC2_D1: U1.B12(PB15)
SDMMC2_D2: U1.A11(PB3)
SDMMC2_D3: U1.B13(PB4)
SDMMC2_D4: U1.A13(PA8)
SDMMC2_D5: U1.B10(PB9)
SDMMC2_D6: U1.C11(PE5)
SDMMC2_D7: U1.B11(PC7)
NetC72_2: C72.2 R31.1 R32.2 U1.AC20(DDR_VREF)
NetR27_1: R27.1 U1.K23(DDR_ZQ)

Not connected (* = marked no-connect by the designer): U1 A2(PH5)* A3(PE13)* A4(PE11)* A5(PF1)* A7(PD5)* A8(PA9)* A14(PF2)* A16(DSI_CKN)* A17(DSI_D1N)* A19(JTDO-TRACESWO)* A20(JTDI)* AA1(PG14)* AA2(PG13)* AA3(PH3)* AA4(PA1)* AA6(PC1)* AA7(PB1)* AA9(PE9)* AA10(PB13)* AA11(PE7)* AA13(PF6)* AA14(PF9)* AA18(PA11)* AB1(PB11)* AB2(PG4)* AB4(PH2)* AB5(PC0)* AB6(PB0)* AB7(PC5)* AB8(PA7)* AB9(PG8)* AB10(PB8)* AB11(PG10)* AB12(PF7)* AB16(USB_DM2)* AB17(USB_DM1)* AB18(USB_RREF)* AB19(PA12)* AC2(PG0)* AC3(PA2)* AC4(PF14)* AC5(PB12)* AC7(PC4)* AC8(PA6)* AC10(PD11)* AC11(PF8)* AC13(PE8)* AC14(PG7)* AC16(USB_DP2)* AC17(USB_DP1)* AC19(OTG_VBUS)* B1(PH15)* B2(PH12)* B3(PH4)* B4(PE12)* B5(PD10)* B6(PD4)* B7(PG15)* B8(PD0)* B9(PD1)* B14(PC6)* B15(DSI_D0N)* B16(DSI_CKP)* B17(DSI_D1P)* B19(NJTRST)* B20(JTCK-SWCLK)* C1(PI0)* C2(PH10)* C3(PH14)* C4(PH11)* C5(PH9)* C6(PE14)* C8(PE1)* C10(PE6)* C15(DSI_D0P)* C19(PA15)* C20(JTMS-SWDIO)* D1(PH13)* D2(PD6)* D3(PE15)* D5(PH8)* D6(PE0)* D7(PF5)* D8(PF0)* D9(PF4)* D10(PD7)* D11(PB7)* D12(PD2)* D13(PC12)* D14(PD3)* D15(PC10)* D16(PC11)* D17(PC9)* D18(PC8)* D19(PE4)* E1(PI3)* E2(PI2)* E3(PI1)* E4(PI4)* F2(PI7)* F3(PI5)* F4(PI6)* G1(PZ1)* G2(PZ4)* G3(PZ0)* G4(PZ3)* H1(PZ6)* H2(PZ5)* H4(PI9)* J2(PD15)* J3(PZ7)* J4(PZ2)* K1(PD9)* K2(PC13)* K3(PD8)* K4(PG12)* K20(DDR_DTO0)* L1(PC15-OSC32_OUT)* L2(PC14-OSC32_IN)* L3(PD14)* L4(PI8)* L21(DDR_DTO1)* M2(BOOT2)* M4(NRST_CORE)* N1(BOOT0)* N2(PA13)* N3(PWR_LP)* N4(BOOT1)* P1(PH0-OSC_IN)* P2(PH1-OSC_OUT)* P4(PI11)* P20(DDR_A15)* R3(PDR_ON)* T1(PI10)* T2(PA14)* T3(PDR_ON_CORE)* T4(PG3)* U1(PF3)* U2(PA3)* U3(ANA0)* U4(ANA1)* V2(PG2)* V3(PA5)* V4(PA4)* W1(PG1)* W2(PC3)* W4(PH7)* Y1(PE2)* Y2(PC2)* Y3(PB10)* Y4(PF15)* Y5(PF13)* Y6(PG5)* Y7(PG11)* Y8(PB5)* Y9(PF12)* Y10(PF11)* Y11(PH6)* Y12(PF10)* Y13(PG9)* Y14(PB6)* Y15(PE10)* Y16(PB2)* Y17(PA10)* Y19(DDR_ATO)*

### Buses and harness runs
bus SDMMC2_D[0..7] = port SDMMC2_D[0..7]

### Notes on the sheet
- eMMC
- POWER - PMIC

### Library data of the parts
C72 C88 = MCD-00006: as C61 on sheet Power_MPU
R27 = MCD-00120: Resistor,240R,0402,1%,1/16W; Manufacturer_Part_Number: RC0402FR-07240RL; Manufacturer: YAGEO; ECCN_US: EAR99; ECCN_EU: NEC; Provided_By: SUBCO
R31 R32 = MCD-00061: Resistor,1K,0402,1%,1/16W; Manufacturer_Part_Number: RC0402FR-071KL; Manufacturer: YAGEO; Provided_By: SUBCO; ECCN_EU: NEC; ECCN_US: EAR99
R37 R38 = MCD-00068: Resistor,1K5,0402,1%,1/16W; Manufacturer_Part_Number: RC0402FR-071K5L; Manufacturer: YAGEO; ECCN_US: EAR99; ECCN_EU: NEC; Provided_By: SUBCO
U1 = MCD-00677: as U1 on sheet Power_MPU

## Sheet 2DDR3L_16bits.SchDoc: 2DDR3L_16bits
size A3; Date: Not used; ApprovedBy: Not used; CheckedBy: Not used; Author: Not used; CompanyName: STMicroelectronics; DrawnBy: Not used; Engineer: Not used; Organization: Not used; Address1: Not used; Address2: Not used; Address3: Not used; Address4: Not used; DocumentNumber: Not used; Revision: Not used; SheetNumber: 7; SheetTotal: 7
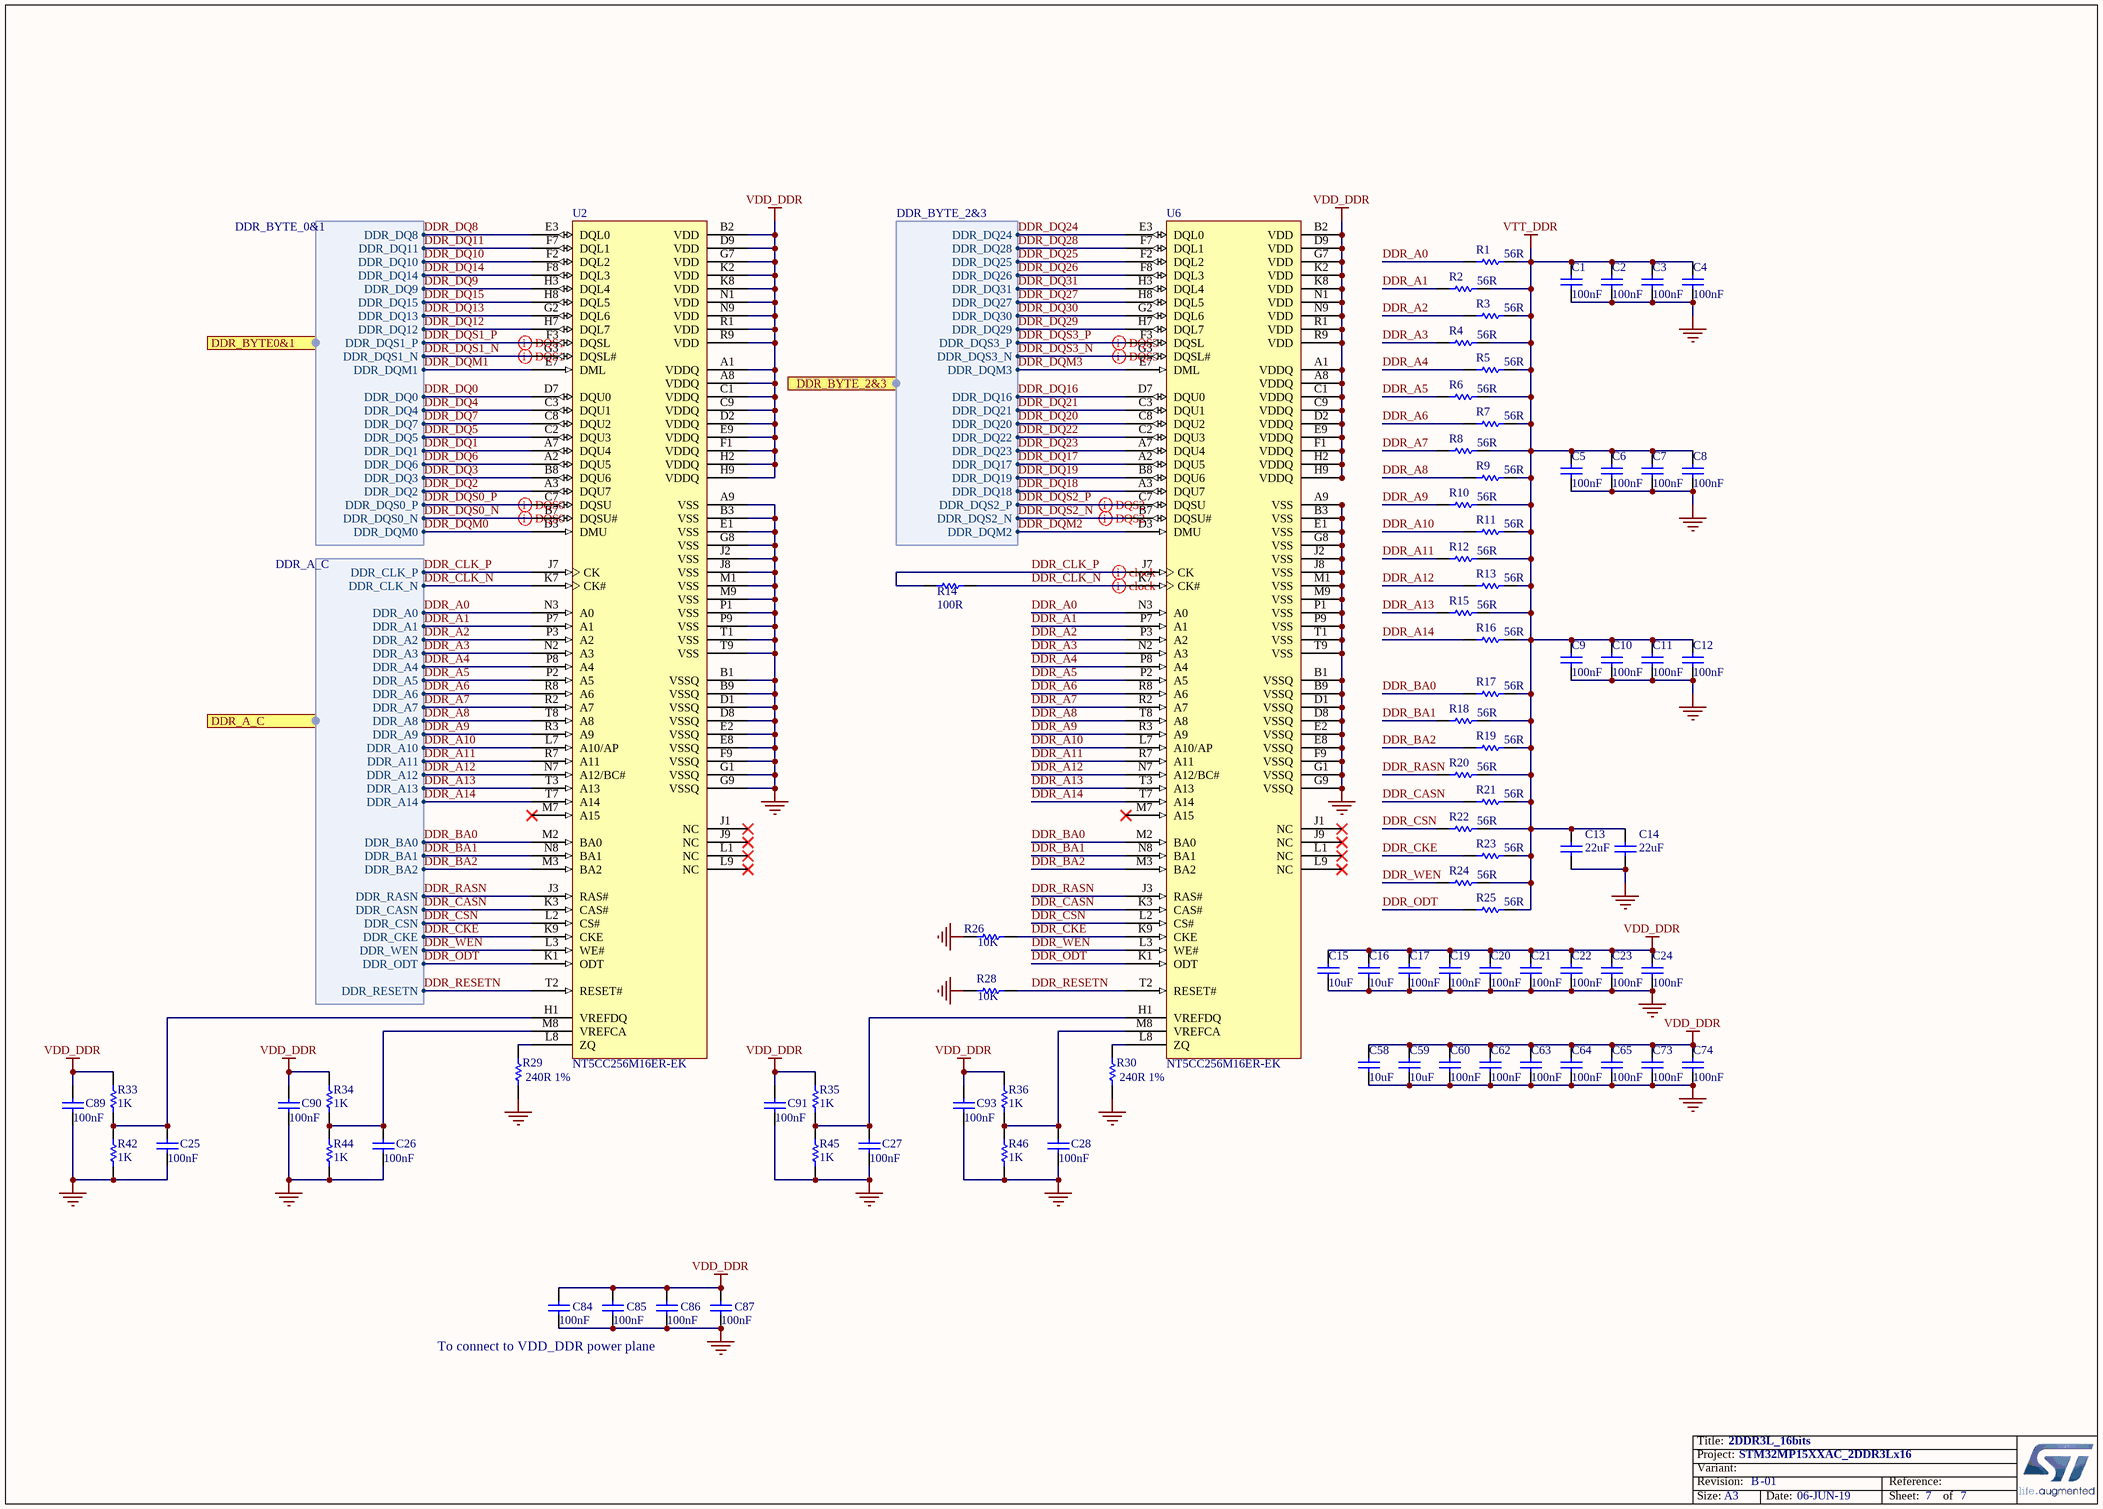
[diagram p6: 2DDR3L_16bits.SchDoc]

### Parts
C1  value 100nF  [C0402]  (hidden comment: Capacitor)
C2  value 100nF  [C0402]  (hidden comment: Capacitor)
C3  value 100nF  [C0402]  (hidden comment: Capacitor)
C4  value 100nF  [C0402]  (hidden comment: Capacitor)
C5  value 100nF  [C0402]  (hidden comment: Capacitor)
C6  value 100nF  [C0402]  (hidden comment: Capacitor)
C7  value 100nF  [C0402]  (hidden comment: Capacitor)
C8  value 100nF  [C0402]  (hidden comment: Capacitor)
C9  value 100nF  [C0402]  (hidden comment: Capacitor)
C10  value 100nF  [C0402]  (hidden comment: Capacitor)
C11  value 100nF  [C0402]  (hidden comment: Capacitor)
C12  value 100nF  [C0402]  (hidden comment: Capacitor)
C13  value 22uF  [C0603]  (hidden comment: Capacitor)
C14  value 22uF  [C0603]  (hidden comment: Capacitor)
C15  value 10uF  [C0603]  (hidden comment: Capacitor)
C16  value 10uF  [C0603]  (hidden comment: Capacitor)
C17  value 100nF  [C0402]  (hidden comment: Capacitor)
C19  value 100nF  [C0402]  (hidden comment: Capacitor)
C20  value 100nF  [C0402]  (hidden comment: Capacitor)
C21  value 100nF  [C0402]  (hidden comment: Capacitor)
C22  value 100nF  [C0402]  (hidden comment: Capacitor)
C23  value 100nF  [C0402]  (hidden comment: Capacitor)
C24  value 100nF  [C0402]  (hidden comment: Capacitor)
C25  value 100nF  [C0402]  (hidden comment: Capacitor)
C26  value 100nF  [C0402]  (hidden comment: Capacitor)
C27  value 100nF  [C0402]  (hidden comment: Capacitor)
C28  value 100nF  [C0402]  (hidden comment: Capacitor)
C58  value 10uF  [C0603]  (hidden comment: Capacitor)
C59  value 10uF  [C0603]  (hidden comment: Capacitor)
C60  value 100nF  [C0402]  (hidden comment: Capacitor)
C62  value 100nF  [C0402]  (hidden comment: Capacitor)
C63  value 100nF  [C0402]  (hidden comment: Capacitor)
C64  value 100nF  [C0402]  (hidden comment: Capacitor)
C65  value 100nF  [C0402]  (hidden comment: Capacitor)
C73  value 100nF  [C0402]  (hidden comment: Capacitor)
C74  value 100nF  [C0402]  (hidden comment: Capacitor)
C84  value 100nF  [C0402]  (hidden comment: Capacitor)
C85  value 100nF  [C0402]  (hidden comment: Capacitor)
C86  value 100nF  [C0402]  (hidden comment: Capacitor)
C87  value 100nF  [C0402]  (hidden comment: Capacitor)
C89  value 100nF  [C0402]  (hidden comment: Capacitor)
C90  value 100nF  [C0402]  (hidden comment: Capacitor)
C91  value 100nF  [C0402]  (hidden comment: Capacitor)
C93  value 100nF  [C0402]  (hidden comment: Capacitor)
R1  value 56R  [R0402]  (hidden comment: Resistor)
R2  value 56R  [R0402]  (hidden comment: Resistor)
R3  value 56R  [R0402]  (hidden comment: Resistor)
R4  value 56R  [R0402]  (hidden comment: Resistor)
R5  value 56R  [R0402]  (hidden comment: Resistor)
R6  value 56R  [R0402]  (hidden comment: Resistor)
R7  value 56R  [R0402]  (hidden comment: Resistor)
R8  value 56R  [R0402]  (hidden comment: Resistor)
R9  value 56R  [R0402]  (hidden comment: Resistor)
R10  value 56R  [R0402]  (hidden comment: Resistor)
R11  value 56R  [R0402]  (hidden comment: Resistor)
R12  value 56R  [R0402]  (hidden comment: Resistor)
R13  value 56R  [R0402]  (hidden comment: Resistor)
R14  value 100R  [R0402]  (hidden comment: Resistor)
R15  value 56R  [R0402]  (hidden comment: Resistor)
R16  value 56R  [R0402]  (hidden comment: Resistor)
R17  value 56R  [R0402]  (hidden comment: Resistor)
R18  value 56R  [R0402]  (hidden comment: Resistor)
R19  value 56R  [R0402]  (hidden comment: Resistor)
R20  value 56R  [R0402]  (hidden comment: Resistor)
R21  value 56R  [R0402]  (hidden comment: Resistor)
R22  value 56R  [R0402]  (hidden comment: Resistor)
R23  value 56R  [R0402]  (hidden comment: Resistor)
R24  value 56R  [R0402]  (hidden comment: Resistor)
R25  value 56R  [R0402]  (hidden comment: Resistor)
R26  value 10K  [R0402]  (hidden comment: Resistor)
R28  value 10K  [R0402]  (hidden comment: Resistor)
R29  value 240R 1%  [R0402]  (hidden comment: Resistor)
R30  value 240R 1%  [R0402]  (hidden comment: Resistor)
R33  value 1K  [R0402]  (hidden comment: Resistor)
R34  value 1K  [R0402]  (hidden comment: Resistor)
R35  value 1K  [R0402]  (hidden comment: Resistor)
R36  value 1K  [R0402]  (hidden comment: Resistor)
R42  value 1K  [R0402]  (hidden comment: Resistor)
R44  value 1K  [R0402]  (hidden comment: Resistor)
R45  value 1K  [R0402]  (hidden comment: Resistor)
R46  value 1K  [R0402]  (hidden comment: Resistor)
U2  NT5CC256M16ER-EK  [ICC_VFBGA96_9x13_P080]
U6  NT5CC256M16ER-EK  [ICC_VFBGA96_9x13_P080]

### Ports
DDR_A_C (harness DDR_A_C), DDR_BYTE0&1 (harness DDR_BYTE_0&1), DDR_BYTE_2&3 (harness DDR_BYTE_2&3)

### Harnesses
DDR_A_C: DDR_A4, DDR_A0, DDR_A2, DDR_A1, DDR_A6, DDR_A3, DDR_A5, DDR_A7, DDR_A8, DDR_A9, DDR_A14, DDR_A10, DDR_A12, DDR_A11, DDR_BA0, DDR_A13, DDR_BA1, DDR_BA2, DDR_RASN, DDR_CASN, DDR_CSN, DDR_CKE, DDR_WEN, DDR_ODT, DDR_CLK_P, DDR_CLK_N, DDR_RESETN
DDR_BYTE_0&1: DDR_DQ9, DDR_DQ8, DDR_DQ10, DDR_DQ11, DDR_DQ13, DDR_DQ14, DDR_DQ15, DDR_DQ12, DDR_DQS1_P, DDR_DQS1_N, DDR_DQ7, DDR_DQM1, DDR_DQ0, DDR_DQ1, DDR_DQ4, DDR_DQ5, DDR_DQ6, DDR_DQ3, DDR_DQ2, DDR_DQS0_P, DDR_DQS0_N, DDR_DQM0
DDR_BYTE_2&3: DDR_DQ24, DDR_DQ28, DDR_DQ25, DDR_DQ26, DDR_DQ31, DDR_DQ27, DDR_DQ30, DDR_DQ29, DDR_DQS3_P, DDR_DQS3_N, DDR_DQM3, DDR_DQ16, DDR_DQ21, DDR_DQ20, DDR_DQ22, DDR_DQ23, DDR_DQ17, DDR_DQ19, DDR_DQ18, DDR_DQS2_P, DDR_DQS2_N, DDR_DQM2

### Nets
GND: C1.2 C2.2 C3.2 C4.2 C5.2 C6.2 C7.2 C8.2 C9.2 C10.2 C11.2 C12.2 C13.1 C14.1 C15.1 C16.1 C17.2 C19.2 C20.2 C21.2 C22.2 C23.2 C24.2 C25.2 C26.2 C27.2 C28.2 C58.1 C59.1 C60.2 C62.2 C63.2 C64.2 C65.2 C73.2 C74.2 C84.2 C85.2 C86.2 C87.2 C89.2 C90.2 C91.2 C93.2 R26.1 R28.1 R29.1 R30.1 R42.1 R44.1 R45.1 R46.1 U2.A9(VSS) U2.B1(VSSQ) U2.B3(VSS) U2.B9(VSSQ) U2.D1(VSSQ) U2.D8(VSSQ) U2.E1(VSS) U2.E2(VSSQ) U2.E8(VSSQ) U2.F9(VSSQ) U2.G1(VSSQ) U2.G8(VSS) U2.G9(VSSQ) U2.J2(VSS) U2.J8(VSS) U2.M1(VSS) U2.M9(VSS) U2.P1(VSS) U2.P9(VSS) U2.T1(VSS) U2.T9(VSS) U6.A9(VSS) U6.B1(VSSQ) U6.B3(VSS) U6.B9(VSSQ) U6.D1(VSSQ) U6.D8(VSSQ) U6.E1(VSS) U6.E2(VSSQ) U6.E8(VSSQ) U6.F9(VSSQ) U6.G1(VSSQ) U6.G8(VSS) U6.G9(VSSQ) U6.J2(VSS) U6.J8(VSS) U6.M1(VSS) U6.M9(VSS) U6.P1(VSS) U6.P9(VSS) U6.T1(VSS) U6.T9(VSS)
VDD_DDR: C15.2 C16.2 C17.1 C19.1 C20.1 C21.1 C22.1 C23.1 C24.1 C58.2 C59.2 C60.1 C62.1 C63.1 C64.1 C65.1 C73.1 C74.1 C84.1 C85.1 C86.1 C87.1 C89.1 C90.1 C91.1 C93.1 R33.2 R34.2 R35.2 R36.2 U2.A1(VDDQ) U2.A8(VDDQ) U2.B2(VDD) U2.C1(VDDQ) U2.C9(VDDQ) U2.D2(VDDQ) U2.D9(VDD) U2.E9(VDDQ) U2.F1(VDDQ) U2.G7(VDD) U2.H2(VDDQ) U2.H9(VDDQ) U2.K2(VDD) U2.K8(VDD) U2.N1(VDD) U2.N9(VDD) U2.R1(VDD) U2.R9(VDD) U6.A1(VDDQ) U6.A8(VDDQ) U6.B2(VDD) U6.C1(VDDQ) U6.C9(VDDQ) U6.D2(VDDQ) U6.D9(VDD) U6.E9(VDDQ) U6.F1(VDDQ) U6.G7(VDD) U6.H2(VDDQ) U6.H9(VDDQ) U6.K2(VDD) U6.K8(VDD) U6.N1(VDD) U6.N9(VDD) U6.R1(VDD) U6.R9(VDD)
VTT_DDR: C1.1 C2.1 C3.1 C4.1 C5.1 C6.1 C7.1 C8.1 C9.1 C10.1 C11.1 C12.1 C13.2 C14.2 R1.2 R2.2 R3.2 R4.2 R5.2 R6.2 R7.2 R8.2 R9.2 R10.2 R11.2 R12.2 R13.2 R15.2 R16.2 R17.2 R18.2 R19.2 R20.2 R21.2 R22.2 R23.2 R24.2 R25.2
DDR_A0: R1.1 U2.N3(A0) U6.N3(A0) ; port DDR_A_C.DDR_A0
DDR_A1: R2.1 U2.P7(A1) U6.P7(A1) ; port DDR_A_C.DDR_A1
DDR_A2: R3.1 U2.P3(A2) U6.P3(A2) ; port DDR_A_C.DDR_A2
DDR_A3: R4.1 U2.N2(A3) U6.N2(A3) ; port DDR_A_C.DDR_A3
DDR_A4: R5.1 U2.P8(A4) U6.P8(A4) ; port DDR_A_C.DDR_A4
DDR_A5: R6.1 U2.P2(A5) U6.P2(A5) ; port DDR_A_C.DDR_A5
DDR_A6: R7.1 U2.R8(A6) U6.R8(A6) ; port DDR_A_C.DDR_A6
DDR_A7: R8.1 U2.R2(A7) U6.R2(A7) ; port DDR_A_C.DDR_A7
DDR_A8: R9.1 U2.T8(A8) U6.T8(A8) ; port DDR_A_C.DDR_A8
DDR_A9: R10.1 U2.R3(A9) U6.R3(A9) ; port DDR_A_C.DDR_A9
DDR_A10: R11.1 U2.L7(A10/AP) U6.L7(A10/AP) ; port DDR_A_C.DDR_A10
DDR_A11: R12.1 U2.R7(A11) U6.R7(A11) ; port DDR_A_C.DDR_A11
DDR_A12: R13.1 U2.N7(A12/BC#) U6.N7(A12/BC#) ; port DDR_A_C.DDR_A12
DDR_A13: R15.1 U2.T3(A13) U6.T3(A13) ; port DDR_A_C.DDR_A13
DDR_A14: R16.1 U2.T7(A14) U6.T7(A14) ; port DDR_A_C.DDR_A14
DDR_BA0: R17.1 U2.M2(BA0) U6.M2(BA0) ; port DDR_A_C.DDR_BA0
DDR_BA1: R18.1 U2.N8(BA1) U6.N8(BA1) ; port DDR_A_C.DDR_BA1
DDR_BA2: R19.1 U2.M3(BA2) U6.M3(BA2) ; port DDR_A_C.DDR_BA2
DDR_CASN: R21.1 U2.K3(CAS#) U6.K3(CAS#) ; port DDR_A_C.DDR_CASN
DDR_CKE: R23.1 R26.2 U2.K9(CKE) U6.K9(CKE) ; port DDR_A_C.DDR_CKE
DDR_CLK_N: R14.2 U2.K7(CK#) U6.K7(CK#) ; port DDR_A_C.DDR_CLK_N
DDR_CLK_P: R14.1 U2.J7(CK) U6.J7(CK) ; port DDR_A_C.DDR_CLK_P
DDR_CSN: R22.1 U2.L2(CS#) U6.L2(CS#) ; port DDR_A_C.DDR_CSN
DDR_DQ0: U2.D7(DQU0) ; port DDR_BYTE0&1.DDR_DQ0
DDR_DQ1: U2.A7(DQU4) ; port DDR_BYTE0&1.DDR_DQ1
DDR_DQ2: U2.A3(DQU7) ; port DDR_BYTE0&1.DDR_DQ2
DDR_DQ3: U2.B8(DQU6) ; port DDR_BYTE0&1.DDR_DQ3
DDR_DQ4: U2.C3(DQU1) ; port DDR_BYTE0&1.DDR_DQ4
DDR_DQ5: U2.C2(DQU3) ; port DDR_BYTE0&1.DDR_DQ5
DDR_DQ6: U2.A2(DQU5) ; port DDR_BYTE0&1.DDR_DQ6
DDR_DQ7: U2.C8(DQU2) ; port DDR_BYTE0&1.DDR_DQ7
DDR_DQ8: U2.E3(DQL0) ; port DDR_BYTE0&1.DDR_DQ8
DDR_DQ9: U2.H3(DQL4) ; port DDR_BYTE0&1.DDR_DQ9
DDR_DQ10: U2.F2(DQL2) ; port DDR_BYTE0&1.DDR_DQ10
DDR_DQ11: U2.F7(DQL1) ; port DDR_BYTE0&1.DDR_DQ11
DDR_DQ12: U2.H7(DQL7) ; port DDR_BYTE0&1.DDR_DQ12
DDR_DQ13: U2.G2(DQL6) ; port DDR_BYTE0&1.DDR_DQ13
DDR_DQ14: U2.F8(DQL3) ; port DDR_BYTE0&1.DDR_DQ14
DDR_DQ15: U2.H8(DQL5) ; port DDR_BYTE0&1.DDR_DQ15
DDR_DQ16: U6.D7(DQU0) ; port DDR_BYTE_2&3.DDR_DQ16
DDR_DQ17: U6.A2(DQU5) ; port DDR_BYTE_2&3.DDR_DQ17
DDR_DQ18: U6.A3(DQU7) ; port DDR_BYTE_2&3.DDR_DQ18
DDR_DQ19: U6.B8(DQU6) ; port DDR_BYTE_2&3.DDR_DQ19
DDR_DQ20: U6.C8(DQU2) ; port DDR_BYTE_2&3.DDR_DQ20
DDR_DQ21: U6.C3(DQU1) ; port DDR_BYTE_2&3.DDR_DQ21
DDR_DQ22: U6.C2(DQU3) ; port DDR_BYTE_2&3.DDR_DQ22
DDR_DQ23: U6.A7(DQU4) ; port DDR_BYTE_2&3.DDR_DQ23
DDR_DQ24: U6.E3(DQL0) ; port DDR_BYTE_2&3.DDR_DQ24
DDR_DQ25: U6.F2(DQL2) ; port DDR_BYTE_2&3.DDR_DQ25
DDR_DQ26: U6.F8(DQL3) ; port DDR_BYTE_2&3.DDR_DQ26
DDR_DQ27: U6.H8(DQL5) ; port DDR_BYTE_2&3.DDR_DQ27
DDR_DQ28: U6.F7(DQL1) ; port DDR_BYTE_2&3.DDR_DQ28
DDR_DQ29: U6.H7(DQL7) ; port DDR_BYTE_2&3.DDR_DQ29
DDR_DQ30: U6.G2(DQL6) ; port DDR_BYTE_2&3.DDR_DQ30
DDR_DQ31: U6.H3(DQL4) ; port DDR_BYTE_2&3.DDR_DQ31
DDR_DQM0: U2.D3(DMU) ; port DDR_BYTE0&1.DDR_DQM0
DDR_DQM1: U2.E7(DML) ; port DDR_BYTE0&1.DDR_DQM1
DDR_DQM2: U6.D3(DMU) ; port DDR_BYTE_2&3.DDR_DQM2
DDR_DQM3: U6.E7(DML) ; port DDR_BYTE_2&3.DDR_DQM3
DDR_DQS0_N: U2.B7(DQSU#) ; port DDR_BYTE0&1.DDR_DQS0_N
DDR_DQS0_P: U2.C7(DQSU) ; port DDR_BYTE0&1.DDR_DQS0_P
DDR_DQS1_N: U2.G3(DQSL#) ; port DDR_BYTE0&1.DDR_DQS1_N
DDR_DQS1_P: U2.F3(DQSL) ; port DDR_BYTE0&1.DDR_DQS1_P
DDR_DQS2_N: U6.B7(DQSU#) ; port DDR_BYTE_2&3.DDR_DQS2_N
DDR_DQS2_P: U6.C7(DQSU) ; port DDR_BYTE_2&3.DDR_DQS2_P
DDR_DQS3_N: U6.G3(DQSL#) ; port DDR_BYTE_2&3.DDR_DQS3_N
DDR_DQS3_P: U6.F3(DQSL) ; port DDR_BYTE_2&3.DDR_DQS3_P
DDR_ODT: R25.1 U2.K1(ODT) U6.K1(ODT) ; port DDR_A_C.DDR_ODT
DDR_RASN: R20.1 U2.J3(RAS#) U6.J3(RAS#) ; port DDR_A_C.DDR_RASN
DDR_RESETN: R28.2 U2.T2(RESET#) U6.T2(RESET#) ; port DDR_A_C.DDR_RESETN
DDR_WEN: R24.1 U2.L3(WE#) U6.L3(WE#) ; port DDR_A_C.DDR_WEN
NetC25_1: C25.1 R33.1 R42.2 U2.H1(VREFDQ)
NetC26_1: C26.1 R34.1 R44.2 U2.M8(VREFCA)
NetC27_1: C27.1 R35.1 R45.2 U6.H1(VREFDQ)
NetC28_1: C28.1 R36.1 R46.2 U6.M8(VREFCA)
NetR29_2: R29.2 U2.L8(ZQ)
NetR30_2: R30.2 U6.L8(ZQ)

Not connected (* = marked no-connect by the designer): U2 J1(NC)* J9(NC)* L1(NC)* L9(NC)* M7(A15)*; U6 J1(NC)* J9(NC)* L1(NC)* L9(NC)* M7(A15)*

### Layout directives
differential pair: DDR_CLK_N, DDR_CLK_P, DDR_DQS0_N, DDR_DQS0_P, DDR_DQS1_N, DDR_DQS1_P, DDR_DQS2_N, DDR_DQS2_P, DDR_DQS3_N, DDR_DQS3_P

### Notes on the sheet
- To connect to VDD_DDR power plane

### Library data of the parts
C1-C12 C17 C19-C28 C60 C62-C65 C73 C74 C84-C87 C89-C91 C93 = MCD-00006: Capacitor, MLCC, 100nF, 16V, X7R, +/-10%, 0402, T=0.5mm; Manufacturer_Part_Number: CC0402KRX7R7BB104; Manufacturer: YAGEO; Alternate_Manufacturer_Part_Number: GCM155R71C104KA55D; Alternate_Manufacturer: MURATA; Provided_By: SUBCO; Order_Code_RS: 616-9701; ECCN_EU: NEC; ECCN_US: EAR99
C13 C14 = MCD-00100: as C29 on sheet Power_PMIC
C15 C16 C58 C59 = MCD-01124: Capacitor, MLCC, 10uF, 10V, X5R, +/-10%, 0603, T=0.8mm; Manufacturer_Part_Number: GRM188R61A106KAAL; Manufacturer: MURATA; Provided_By: SUBCO; Order_Code_RS: 170-6258; ECCN_EU: NEC; ECCN_US: EAR99
R1-R13 R15-R25 = MCD-00054: Resistor,56R,0402,1%,1/16W; Manufacturer_Part_Number: RC0402FR-0756RL; Manufacturer: YAGEO; Provided_By: SUBCO; ECCN_EU: NEC; ECCN_US: EAR99
R14 = MCD-00067: Resistor,100R,0402,1%,1/16W; Manufacturer_Part_Number: RC0402FR-07100RL; Manufacturer: YAGEO; Provided_By: SUBCO; ECCN_EU: NEC; ECCN_US: EAR99
R26 R28 = MCD-00053: as R40 on sheet eMMC
R29 R30 = MCD-00120: Resistor,240R,0402,1%,1/16W; Manufacturer_Part_Number: RC0402FR-07240RL; Manufacturer: YAGEO; Provided_By: SUBCO; ECCN_EU: NEC; ECCN_US: EAR99
R33-R36 R42 R44-R46 = MCD-00061: as R31 on sheet STM32_MPU_IOs
U2 U6 = MCD-01811: Memory,DDR3L,4Gb,256Mbx16,933Mhz,1V35,TFBGA; Part_Type: IC; Manufacturer: NANYA; BMS_Part_Number: 9171435; ECCN_US: tbd; Provided_By: SUBCO

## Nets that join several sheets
3V3: Power_PMIC (5 pins), eMMC (6 pins)
GND: Power_PMIC (27 pins), Power_MPU (86 pins), eMMC (17 pins), STM32_MPU_IOs (5 pins), 2DDR3L_16bits (94 pins)
VDD: Power_PMIC (C38.2 L3.2 U4.31 U4.42), Power_MPU (15 pins), eMMC (8 pins), STM32_MPU_IOs (R37.1 R38.1)
VDD_CORE: Power_PMIC (C34.2 L1.2 U4.5), Power_MPU (27 pins)
VDD_DDR: Power_PMIC (5 pins), Power_MPU (16 pins), STM32_MPU_IOs (C88.2 R31.2), 2DDR3L_16bits (66 pins)
VDD_USB: Power_PMIC (C52.2 U4.39), Power_MPU (C71.2 U1.AA15 U1.AA17)
VDDA: Power_PMIC (C49.2 U4.20), Power_MPU (C70.2 R41.1 U1.1H1)
VTT_DDR: Power_PMIC (C46.2 U4.14), 2DDR3L_16bits (38 pins)
DDR_A0: STM32_MPU_IOs (U1.L20), 2DDR3L_16bits (R1.1 U2.N3 U6.N3)
DDR_A1: STM32_MPU_IOs (U1.P22), 2DDR3L_16bits (R2.1 U2.P7 U6.P7)
DDR_A2: STM32_MPU_IOs (U1.J20), 2DDR3L_16bits (R3.1 U2.P3 U6.P3)
DDR_A3: STM32_MPU_IOs (U1.K22), 2DDR3L_16bits (R4.1 U2.N2 U6.N2)
DDR_A4: STM32_MPU_IOs (U1.V20), 2DDR3L_16bits (R5.1 U2.P8 U6.P8)
DDR_A5: STM32_MPU_IOs (U1.H20), 2DDR3L_16bits (R6.1 U2.P2 U6.P2)
DDR_A6: STM32_MPU_IOs (U1.W20), 2DDR3L_16bits (R7.1 U2.R8 U6.R8)
DDR_A7: STM32_MPU_IOs (U1.E20), 2DDR3L_16bits (R8.1 U2.R2 U6.R2)
DDR_A8: STM32_MPU_IOs (U1.Y20), 2DDR3L_16bits (R9.1 U2.T8 U6.T8)
DDR_A9: STM32_MPU_IOs (U1.G20), 2DDR3L_16bits (R10.1 U2.R3 U6.R3)
DDR_A10: STM32_MPU_IOs (U1.R22), 2DDR3L_16bits (R11.1 U2.L7 U6.L7)
DDR_A11: STM32_MPU_IOs (U1.R20), 2DDR3L_16bits (R12.1 U2.R7 U6.R7)
DDR_A12: STM32_MPU_IOs (U1.P23), 2DDR3L_16bits (R13.1 U2.N7 U6.N7)
DDR_A13: STM32_MPU_IOs (U1.F20), 2DDR3L_16bits (R15.1 U2.T3 U6.T3)
DDR_A14: STM32_MPU_IOs (U1.R21), 2DDR3L_16bits (R16.1 U2.T7 U6.T7)
DDR_BA0: STM32_MPU_IOs (U1.L23), 2DDR3L_16bits (R17.1 U2.M2 U6.M2)
DDR_BA1: STM32_MPU_IOs (U1.U20), 2DDR3L_16bits (R18.1 U2.N8 U6.N8)
DDR_BA2: STM32_MPU_IOs (U1.M21), 2DDR3L_16bits (R19.1 U2.M3 U6.M3)
DDR_CASN: STM32_MPU_IOs (U1.N20), 2DDR3L_16bits (R21.1 U2.K3 U6.K3)
DDR_CKE: STM32_MPU_IOs (U1.T20), 2DDR3L_16bits (R23.1 R26.2 U2.K9 U6.K9)
DDR_CLK_N: STM32_MPU_IOs (U1.N23), 2DDR3L_16bits (R14.2 U2.K7 U6.K7)
DDR_CLK_P: STM32_MPU_IOs (U1.N22), 2DDR3L_16bits (R14.1 U2.J7 U6.J7)
DDR_CSN: STM32_MPU_IOs (U1.M22), 2DDR3L_16bits (R22.1 U2.L2 U6.L2)
DDR_DQ0: STM32_MPU_IOs (U1.E22), 2DDR3L_16bits (U2.D7)
DDR_DQ1: STM32_MPU_IOs (U1.F22), 2DDR3L_16bits (U2.A7)
DDR_DQ2: STM32_MPU_IOs (U1.H21), 2DDR3L_16bits (U2.A3)
DDR_DQ3: STM32_MPU_IOs (U1.E21), 2DDR3L_16bits (U2.B8)
DDR_DQ4: STM32_MPU_IOs (U1.J21), 2DDR3L_16bits (U2.C3)
DDR_DQ5: STM32_MPU_IOs (U1.J22), 2DDR3L_16bits (U2.C2)
DDR_DQ6: STM32_MPU_IOs (U1.H22), 2DDR3L_16bits (U2.A2)
DDR_DQ7: STM32_MPU_IOs (U1.G21), 2DDR3L_16bits (U2.C8)
DDR_DQ8: STM32_MPU_IOs (U1.T21), 2DDR3L_16bits (U2.E3)
DDR_DQ9: STM32_MPU_IOs (U1.U21), 2DDR3L_16bits (U2.H3)
DDR_DQ10: STM32_MPU_IOs (U1.T22), 2DDR3L_16bits (U2.F2)
DDR_DQ11: STM32_MPU_IOs (U1.W21), 2DDR3L_16bits (U2.F7)
DDR_DQ12: STM32_MPU_IOs (U1.W23), 2DDR3L_16bits (U2.H7)
DDR_DQ13: STM32_MPU_IOs (U1.T23), 2DDR3L_16bits (U2.G2)
DDR_DQ14: STM32_MPU_IOs (U1.W22), 2DDR3L_16bits (U2.F8)
DDR_DQ15: STM32_MPU_IOs (U1.Y21), 2DDR3L_16bits (U2.H8)
DDR_DQ16: STM32_MPU_IOs (U1.B22), 2DDR3L_16bits (U6.D7)
DDR_DQ17: STM32_MPU_IOs (U1.D22), 2DDR3L_16bits (U6.A2)
DDR_DQ18: STM32_MPU_IOs (U1.D23), 2DDR3L_16bits (U6.A3)
DDR_DQ19: STM32_MPU_IOs (U1.B21), 2DDR3L_16bits (U6.B8)
DDR_DQ20: STM32_MPU_IOs (U1.A21), 2DDR3L_16bits (U6.C8)
DDR_DQ21: STM32_MPU_IOs (U1.E23), 2DDR3L_16bits (U6.C3)
DDR_DQ22: STM32_MPU_IOs (U1.D21), 2DDR3L_16bits (U6.C2)
DDR_DQ23: STM32_MPU_IOs (U1.A22), 2DDR3L_16bits (U6.A7)
DDR_DQ24: STM32_MPU_IOs (U1.Y23), 2DDR3L_16bits (U6.E3)
DDR_DQ25: STM32_MPU_IOs (U1.Y22), 2DDR3L_16bits (U6.F2)
DDR_DQ26: STM32_MPU_IOs (U1.AB21), 2DDR3L_16bits (U6.F8)
DDR_DQ27: STM32_MPU_IOs (U1.AB20), 2DDR3L_16bits (U6.H8)
DDR_DQ28: STM32_MPU_IOs (U1.AC22), 2DDR3L_16bits (U6.F7)
DDR_DQ29: STM32_MPU_IOs (U1.AC21), 2DDR3L_16bits (U6.H7)
DDR_DQ30: STM32_MPU_IOs (U1.AA23), 2DDR3L_16bits (U6.G2)
DDR_DQ31: STM32_MPU_IOs (U1.AA22), 2DDR3L_16bits (U6.H3)
DDR_DQM0: STM32_MPU_IOs (U1.H23), 2DDR3L_16bits (U2.D3)
DDR_DQM1: STM32_MPU_IOs (U1.V22), 2DDR3L_16bits (U2.E7)
DDR_DQM2: STM32_MPU_IOs (U1.C23), 2DDR3L_16bits (U6.D3)
DDR_DQM3: STM32_MPU_IOs (U1.AA20), 2DDR3L_16bits (U6.E7)
DDR_DQS0_N: STM32_MPU_IOs (U1.G23), 2DDR3L_16bits (U2.B7)
DDR_DQS0_P: STM32_MPU_IOs (U1.G22), 2DDR3L_16bits (U2.C7)
DDR_DQS1_N: STM32_MPU_IOs (U1.U23), 2DDR3L_16bits (U2.G3)
DDR_DQS1_P: STM32_MPU_IOs (U1.U22), 2DDR3L_16bits (U2.F3)
DDR_DQS2_N: STM32_MPU_IOs (U1.B23), 2DDR3L_16bits (U6.B7)
DDR_DQS2_P: STM32_MPU_IOs (U1.C22), 2DDR3L_16bits (U6.C7)
DDR_DQS3_N: STM32_MPU_IOs (U1.AB23), 2DDR3L_16bits (U6.G3)
DDR_DQS3_P: STM32_MPU_IOs (U1.AB22), 2DDR3L_16bits (U6.F3)
DDR_ODT: STM32_MPU_IOs (U1.L22), 2DDR3L_16bits (R25.1 U2.K1 U6.K1)
DDR_RASN: STM32_MPU_IOs (U1.N21), 2DDR3L_16bits (R20.1 U2.J3 U6.J3)
DDR_RESETN: STM32_MPU_IOs (U1.D20), 2DDR3L_16bits (R28.2 U2.T2 U6.T2)
DDR_WEN: STM32_MPU_IOs (U1.M20), 2DDR3L_16bits (R24.1 U2.L3 U6.L3)
I2C4_SCL: Power_PMIC (U4.4), STM32_MPU_IOs (R37.2 U1.Y18)
I2C4_SDA: Power_PMIC (U4.3), STM32_MPU_IOs (R38.2 U1.AA19)
NRST: Power_PMIC (U4.1), STM32_MPU_IOs (U1.M3)
PA0_WKUP: Power_PMIC (U4.43), STM32_MPU_IOs (U1.AB3)
PWR_ON: Power_PMIC (U4.44), STM32_MPU_IOs (U1.R2)

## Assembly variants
Example: all parts fitted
